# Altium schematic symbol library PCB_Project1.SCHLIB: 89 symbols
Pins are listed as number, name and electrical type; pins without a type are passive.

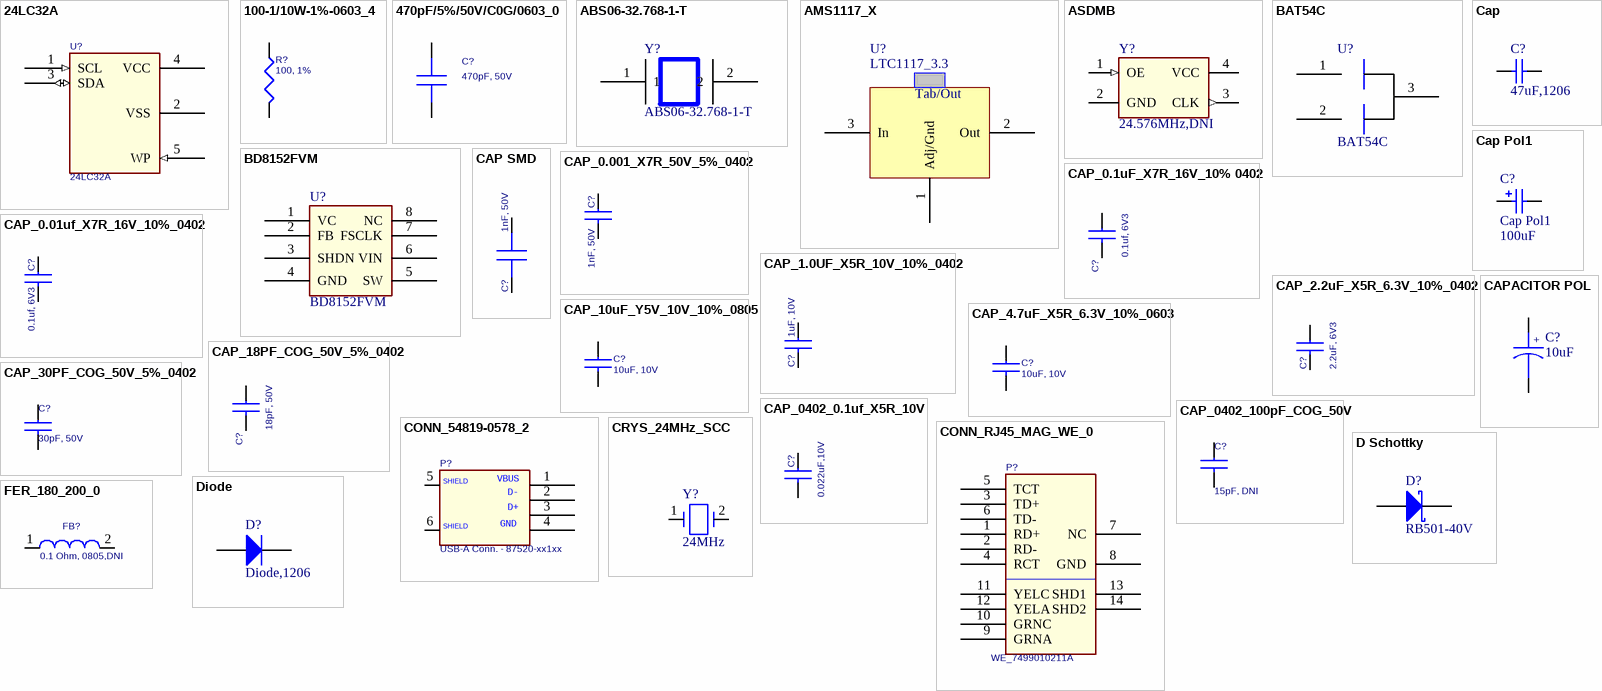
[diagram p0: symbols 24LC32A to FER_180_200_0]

## 24LC32A
designator U?
IC EEPROM 32KBIT 400KHZ SOT23-5; Manufacturer: Microchip Technology; Manufacturer Part Number: 24LC32AT-I/OT; Format - Memory: EEPROMs - Serial; Memory Size: 32K (4K x 8); Interface: I²C, 2-Wire Serial; Voltage - Supply: 2.5 V ~ 5.5 V
footprint SOT23-5/24LC32AT-I /SOT-23-5 (Footprint not found)
pins: 1 SCL (in), 2 VSS (power), 3 SDA (io), 4 VCC (power), 5 WP (in)

## 100-1/10W-1%-0603_4
designator R?, comment 100, 1%
RES 100 OHM 1/10W 5% 0402 SMD; PART#: Rohm MCR03EZPFX1000; Manufacturer: Panasonic Electronic Components; Manufacturer Part Number: ERJ-2RKF1000X; Resistance (Ohms): 100; Power (Watts): 0.1W, 1/10W; Temperature Coefficient: ?00ppm/°C
footprint 402
footprint R0402
pins: 1, 2

## 470pF/5%/50V/C0G/0603_0
designator C?, comment 470pF, 50V
CAP CER 470PF 50V 10% X7R 0402; Manufacturer: Murata Electronics North America; Manufacturer Part Number: GRM155R71H471KA01D; Tolerance: ?0%
footprint 402
footprint 402
pins: 1, 2

## ABS06-32.768-1-T
designator Y?
footprint SMD/ABS06-32.768KHZ-1-T (Footprint not found)
pins: 1, 2

## AMS1117_X
designator U?, comment LTC1117_3.3
footprint SOT223
pins: 1 Adj/Gnd, 2 Out, 3 In

## ASDMB
designator Y?, comment 24.576MHz,DNI
Manufacturer: Abracon Corporation; Manufacturer Part Number: ASDMB-24.576MHZ-LC-T; Function: Standby (Power Down); Output: CMOS; Voltage - Supply: 1.8 V ~ 3.3 V; Frequency Stability: ?0ppm; Current - Supply (Max): 16mA; Current - Supply (Disable) (Max): 15µA
footprint OSC4_61X65LS_79X98SMD
pins: 1 OE (in), 2 GND (power), 3 CLK (out), 4 VCC (power)

## BAT54C
designator U?
footprint SOT-23/BAT54C (Footprint not found)
pins: 1, 2, 3

## BD8152FVM
designator U?
footprint MSOP8/BD8152FVM (Footprint not found)
pins: 1 VC, 2 FB, 3 SHDN, 4 GND, 5 SW, 6 VIN, 7 FSCLK, 8 NC

## Cap
designator C?, comment 47uF,1206
Capacitor
footprint 1206 (Footprint not found)
pins: 1, 2

## Cap Pol1
designator C?  value 100uF
Polarized Capacitor (Radial)
simulation model CAP (Capacitor)
signal-integrity model Cap Pol
footprint RD205SMD_250D (Footprint not found)
pins: 1, 2
1 alternate drawing of the same symbol

## CAP SMD
designator C?, comment 1nF, 50V
CAP CER 1000PF 16V 10% X7R 0402; Manufacturer: Yageo; Manufacturer Part Number: CC0402KRX7R7BB102; Tolerance: ?0%
footprint 402
pins: 1, 2

## CAP_0.001_X7R_50V_5%_0402
designator C?, comment 1nF, 50V
CAP CER 1000PF 16V 10% X7R 0402; Manufacturer: Yageo; Manufacturer Part Number: CC0402KRX7R7BB102; Tolerance: ?0%
footprint 402
footprint 402
pins: 1, 2

## CAP_0.1uF_X7R_16V_10% 0402
designator C?, comment 0.1uf, 6V3
CAP CER 0.1UF 6.3V 10% X5R 0402; Manufacturer: TDK Corporation; Manufacturer Part Number: C1005X5R0J104K050BA; Capacitance: 0.1µF; Tolerance: ?0%
footprint 402
footprint 402
pins: 1, 2

## CAP_0.01uf_X7R_16V_10%_0402
designator C?, comment 0.1uf, 6V3
CAP CER 0.1UF 6.3V 10% X5R 0402; Manufacturer: TDK Corporation; Manufacturer Part Number: C1005X5R0J104K050BA; Capacitance: 0.1µF; Tolerance: ?0%
footprint 402
footprint 402
pins: 1, 2

## CAP_1.0UF_X5R_10V_10%_0402
designator C?, comment 1uF, 10V
CAP CER 1UF 10V 10% X5R 0402; Manufacturer: AVX Corporation; Manufacturer Part Number: 0402ZD105KAT2A; Capacitance: 1.0µF; Tolerance: ?0%
footprint 402
footprint 402
pins: 1, 2

## CAP_2.2uF_X5R_6.3V_10%_0402
designator C?, comment 2.2uF, 6V3
CAP CER 2.2UF 6.3V 10% X5R 0402; Manufacturer: TDK Corporation; Manufacturer Part Number: C1005X5R0J225K050BC; Capacitance: 2.2µF; Tolerance: ?0%
footprint 0805 (Footprint not found)
footprint 402
pins: 1, 2

## CAP_4.7uF_X5R_6.3V_10%_0603
designator C?, comment 10uF, 10V
CAP CER 10UF 10V Y5V 0805; Manufacturer: TDK Corporation; Manufacturer Part Number: C2012Y5V1A106Z; Capacitance: 10µF; Tolerance: -20%, +80%; Temperature Coefficient: Y5V (F)
footprint 805
pins: 1, 2

## CAP_10uF_Y5V_10V_10%_0805
designator C?, comment 10uF, 10V
CAP CER 10UF 10V Y5V 0805; Manufacturer: TDK Corporation; Manufacturer Part Number: C2012Y5V1A106Z; Capacitance: 10µF; Tolerance: -20%, +80%; Temperature Coefficient: Y5V (F)
footprint 805
pins: 1, 2

## CAP_18PF_COG_50V_5%_0402
designator C?, comment 18pF, 50V
CAP CER 18PF 50V 5% NP0 0402; Manufacturer: TDK Corporation; Manufacturer Part Number: C1005C0G1H180J050BA; Tolerance: ?%; Temperature Coefficient: C0G, NP0
footprint 402
footprint 402
pins: 1, 2

## CAP_30PF_COG_50V_5%_0402
designator C?, comment 30pF, 50V
CAP CER 30PF 50V 5% NP0 0402; Manufacturer: TDK Corporation; Manufacturer Part Number: C1005C0G1H300J; Tolerance: ?%; Temperature Coefficient: C0G, NP0
footprint 402
footprint 402
pins: 1, 2

## CAP_0402_0.1uf_X5R_10V
designator C?, comment 0.022uF,10V
CAP CER 0.022UF 10V 10% X7R 0402; Manufacturer: Taiyo Yuden; Manufacturer Part Number: LMK105B7223KV-F; Capacitance: 0.022µF; Tolerance: ?0%
footprint 402
pins: 1, 2

## CAP_0402_100pF_COG_50V
designator C?, comment 15pF, DNI
CAP CER 15PF 50V 5% NP0 0402; Manufacturer: TDK Corporation; Manufacturer Part Number: C1005C0G1H150J050BA; Tolerance: ?%; Temperature Coefficient: C0G, NP0
footprint 402
pins: 1, 2

## CAPACITOR POL
designator C?, comment 10uF
Capacitor
footprint 3528T (Footprint not found)
pins: 1, 2

## CONN_54819-0578_2
designator P?, comment USB-A Conn. - 87520-xx1xx
CONN RCPT USB TYPE A R/A PCB; Manufacturer: FCI; Manufacturer Part Number: 87520-0010BLF; CLASS: IO; TN: 224-0234-000; Number of Contacts: 4; Gender: Receptacle; Specifications: USB 2.0
footprint usb_a_sh
pins: 1 P1, 2 P2, 3 P3, 4 P4, 5 SHELD1, 6 PAD4

## CONN_RJ45_MAG_WE_0
designator P?, comment WE_7499010211A
WE-RJ45 LAN Transformer
footprint RJ45-BEL_J1-SHLD
footprint RJ45-7499010211A
pins: 1 RD+, 2 RD-, 3 TD+, 4 RCT, 5 TCT, 6 TD-, 7 NC, 8 GND, 9 GRNA, 10 GRNC, 11 YELC, 12 YELA, 13 SHD1, 14 SHD2

## CRYS_24MHz_SCC
designator Y?, comment 24MHz
CRYSTAL 24.000MHZ 18PF SMD; Manufacturer: TXC CORPORATION; Manufacturer Part Number: 7A-24.000MAAJ-T; Frequency Stability: ?0ppm; ESR (Equivalent Series Resistance): 50 Ohm; Operating Mode: Fundamental
footprint XTAL150SMD_125X196
pins: 1, 2

## D Schottky
designator D?, comment RB501-40V
Schottky Diode
footprint DSO-C2/X2.3 (DO-214-AA/SMB; 2 C-Bend Leads; Body 5.3 x 3.6 mm, inc. leads (LxW))
simulation model SKYDIODE (Diode)
signal-integrity model D Schottky
pins: 1 A, 2 K

## Diode
designator D?, comment Diode,1206
Default Diode
simulation model DIODE (Diode)
signal-integrity model Diode
footprint 1206P (Footprint not found)
pins: 1 A, 2 K

## FER_180_200_0
designator FB?, comment 0.1 Ohm, 0805,DNI
RES .10 OHM 1/8W 5% 0805; Manufacturer: CTS Resistor Products; Manufacturer Part Number: 73L3R10J; Resistance (Ohms): 0.1; Power (Watts): 0.125W, 1/8W; Temperature Coefficient: ?00ppm/°C; Tolerance: ?%
footprint SM-7351-IND-0805
pins: 1, 2

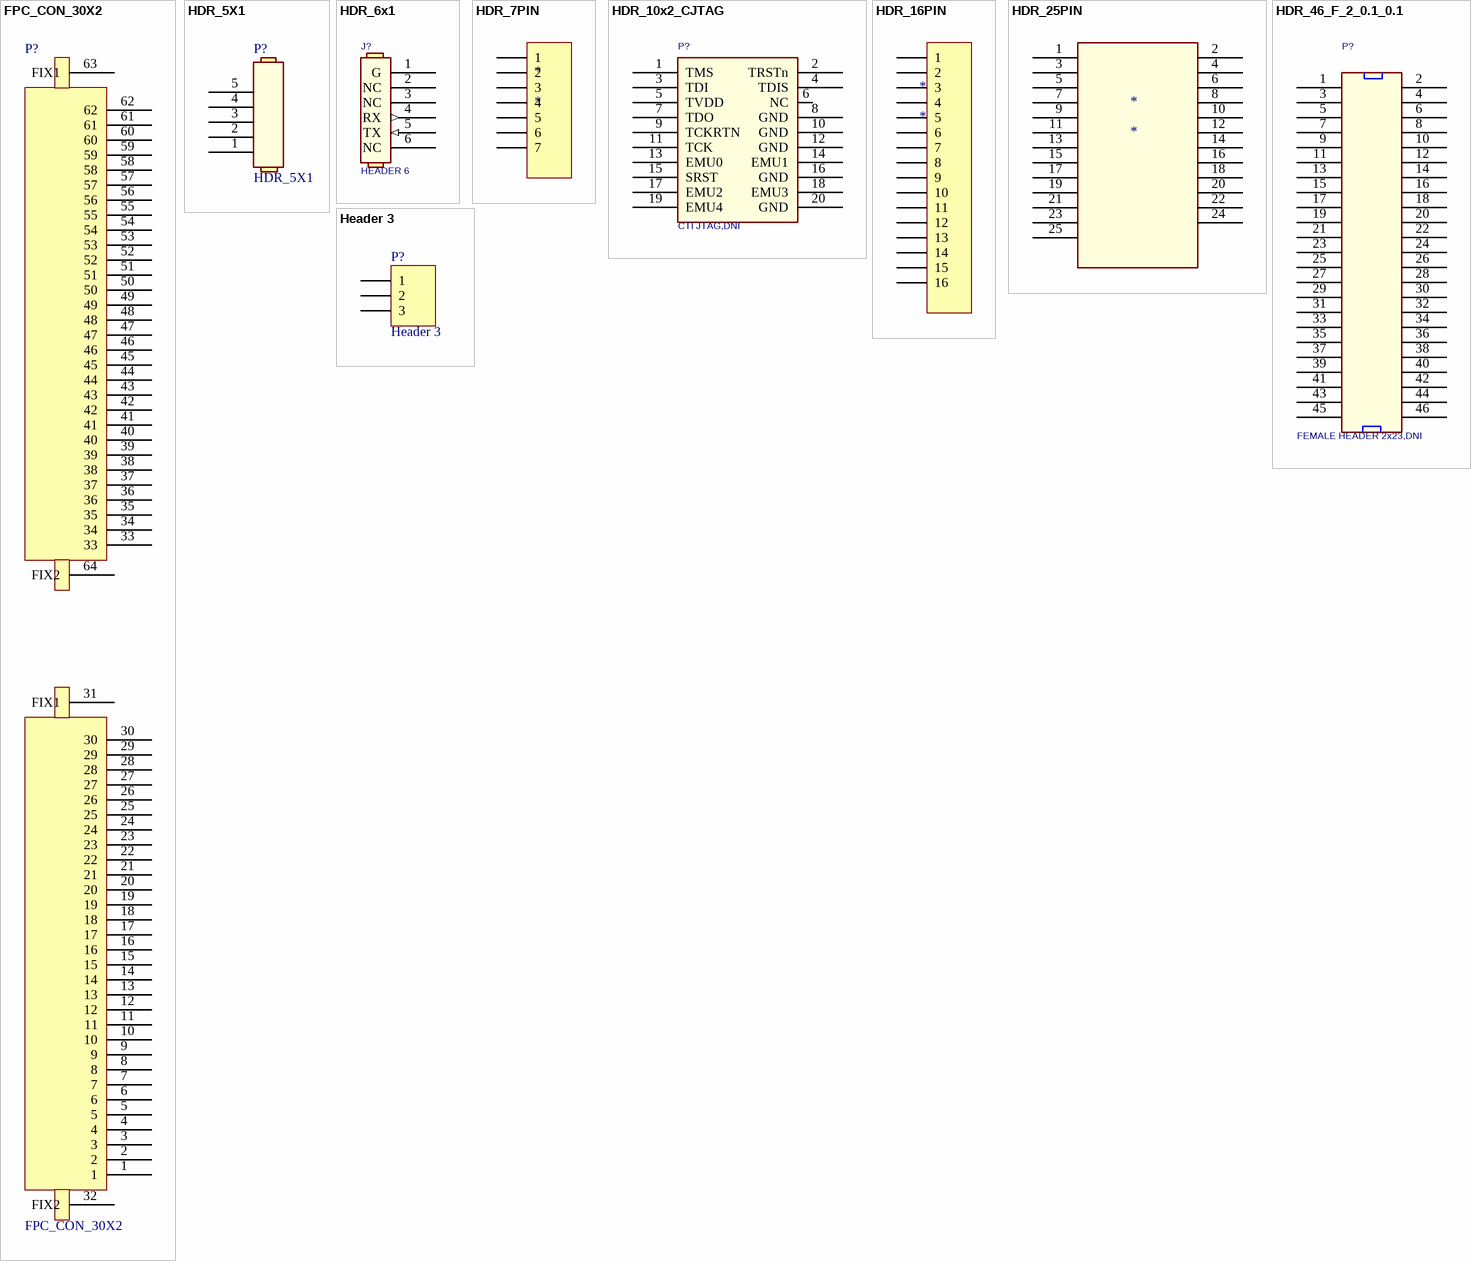
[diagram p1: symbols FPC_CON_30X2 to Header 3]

## FPC_CON_30X2
designator P?
footprint FPC_CON_30X2 (Footprint not found)
pins: 1, 2, 3, 4, 5, 6, 7, 8, 9, 10, 11, 12, 13, 14, 15, 16, 17, 18, 19, 20, 21, 22, 23, 24, 25, 26, 27, 28, 29, 30, 31 FIX1, 32 FIX2, 33, 34, 35, 36, 37, 38, 39, 40, 41, 42, 43, 44, 45, 46, 47, 48, 49, 50, 51, 52, 53, 54, 55, 56, 57, 58, 59, 60, 61, 62, 63 FIX1, 64 FIX2

## HDR_5X1
designator P?
footprint HDR_5X1 (Footprint not found)
pins: 1 (power), 2, 3, 4, 5

## HDR_6x1
designator J?, comment HEADER 6
CONN HEADER 6POS, VERTICAL,  .100 STR TIN; Manufacturer: Samtec Inc; Manufacturer Part Number: FTR-110-03-G-D-06; Connector Type: Unshrouded; Number of Positions: 20; Number of Positions Loaded: 19; Pitch: 0.050" (1.27mm); Row Spacing: 0.100" (2.54mm)
footprint SIP6
pins: 1 G (power), 2 NC, 3 NC, 4 RX (out), 5 TX (in), 6 NC

## HDR_7PIN
designator *
pins: 1, 2, 3, 4, 5, 6, 7

## HDR_10x2_CJTAG
designator P?, comment CTI JTAG,DNI
Dual Line Header 10x2pin Tin; Manufacturer: Samtec Inc; Manufacturer Part Number: FTR-110-03-G-D-06; Connector Type: Unshrouded; Number of Positions: 20; Number of Positions Loaded: 19; Pitch: 0.050" (1.27mm); Row Spacing: 0.100" (2.54mm)
footprint HEADER10X2_SMD
pins: 1 TMS, 2 TRSTn, 3 TDI, 4 TDIS, 5 TVDD, 6 NC, 7 TDO, 8 GND (power), 9 TCKRTN, 10 GND (power), 11 TCK, 12 GND (power), 13 EMU0, 14 EMU1, 15 SRST, 16 GND (power), 17 EMU2, 18 EMU3, 19 EMU4, 20 GND (power)

## HDR_16PIN
designator *
pins: 1, 2, 3, 4, 5, 6, 7, 8, 9, 10, 11, 12, 13, 14, 15, 16

## HDR_25PIN
designator *
pins: 1, 2, 3, 4, 5, 6, 7, 8, 9, 10 (power), 11, 12 (power), 13, 14, 15, 16 (power), 17, 18, 19, 20 (power), 21, 22 (power), 23, 24, 25

## HDR_46_F_2_0.1_0.1
designator P?, comment FEMALE HEADER 2x23,DNI
CONN HEADER FMAL 46PS.1" DL GOLD; Manufacturer: Sullins Connector Solutions; Manufacturer Part Number: PPPC232LFBN-RC; Number of Positions: 46; Number of Positions Loaded: All; Pitch: 0.100" (2.54mm)
footprint HEADER23X2
pins: 1, 2 26, 3 2, 4 27, 5 3, 6 28, 7 4, 8 29, 9 5, 10 30, 11 6, 12 31, 13 7, 14 32, 15 8, 16 33, 17 9, 18 34, 19 10, 20 35, 21 11, 22 36, 23 12, 24 37, 25 13, 26 38, 27 14, 28 39, 29 15, 30 40, 31 16, 32 41, 33 17, 34 42, 35 18, 36 43, 37 19, 38 44, 39 20, 40 45, 41 21, 42 46, 43 22, 44 47, 45 23, 46 48

## Header 3
designator P?
Header, 3-Pin
footprint HDR1X3 (Connector; Header; 3 Position)
signal-integrity model Connector
pins: 1, 2, 3

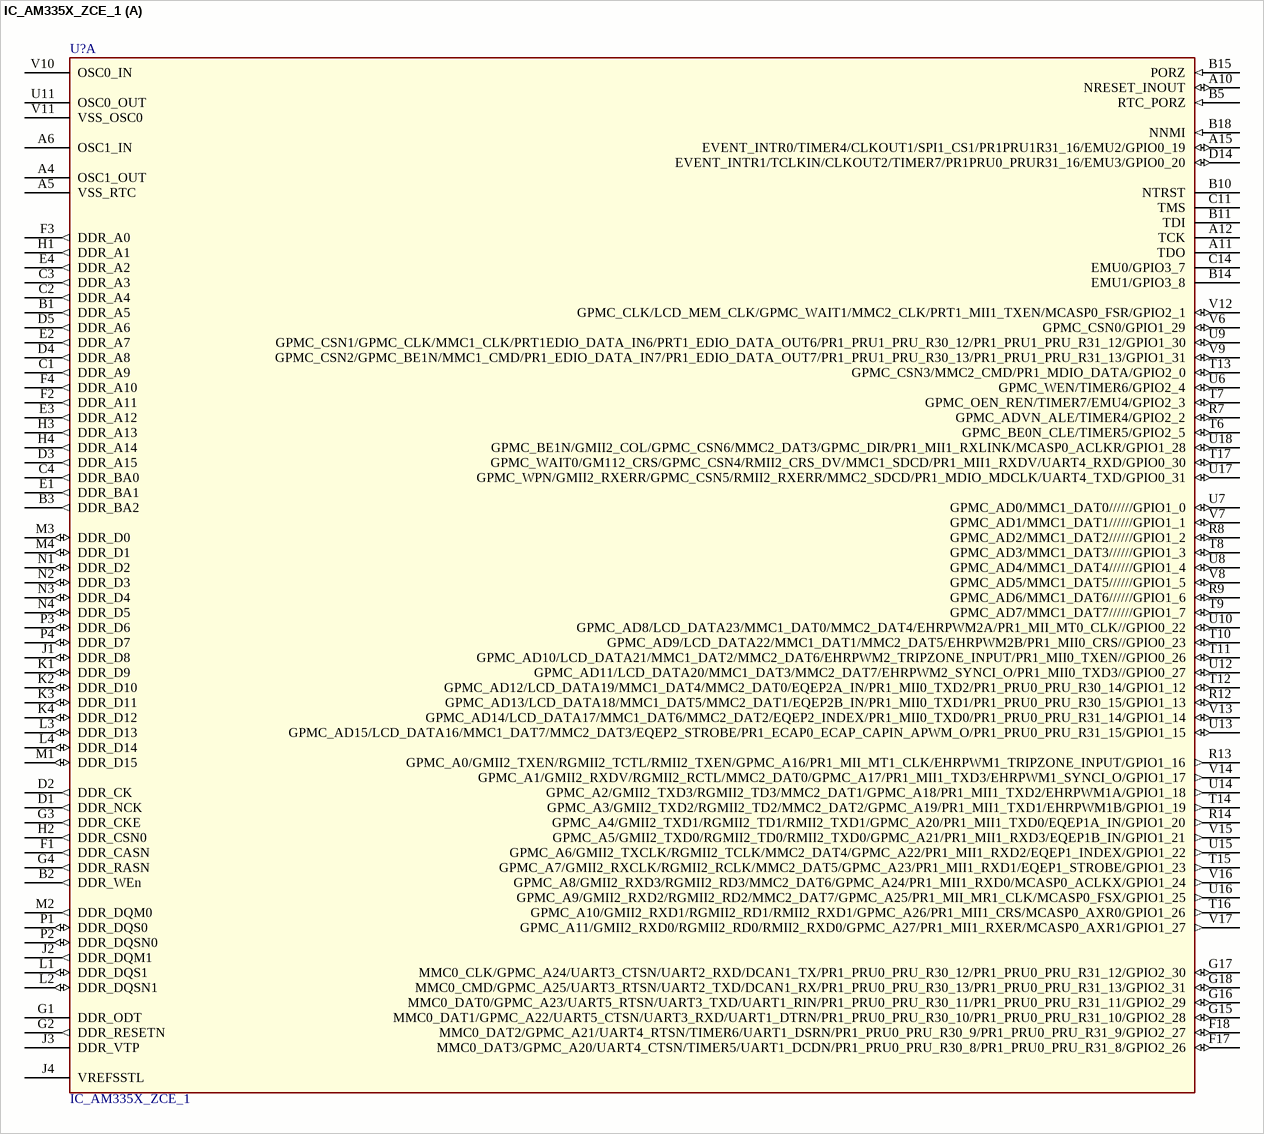
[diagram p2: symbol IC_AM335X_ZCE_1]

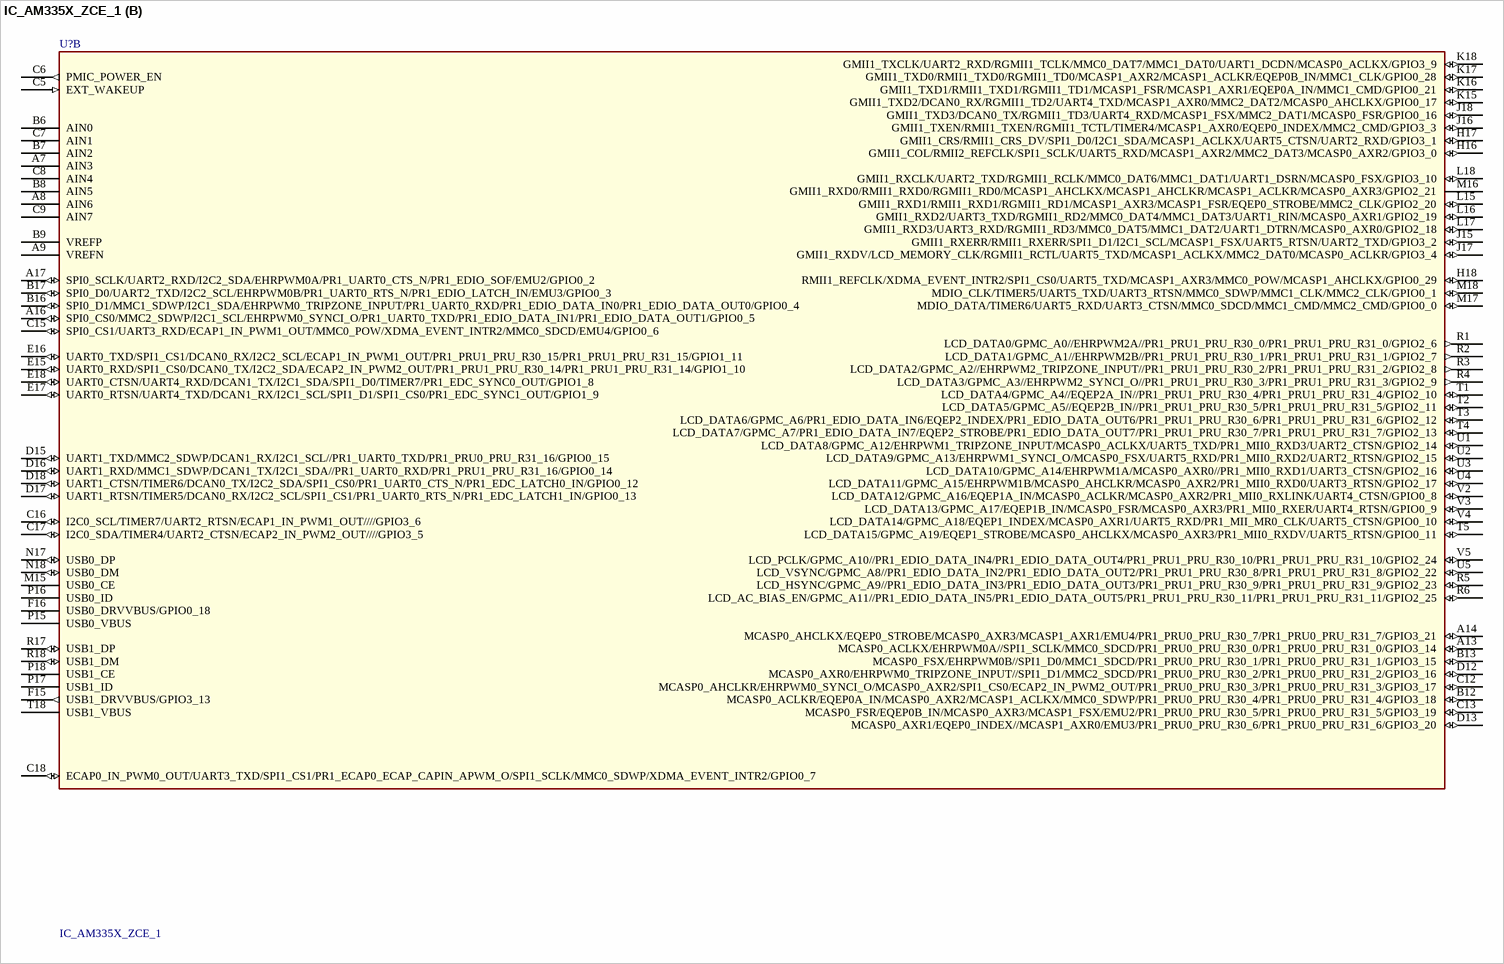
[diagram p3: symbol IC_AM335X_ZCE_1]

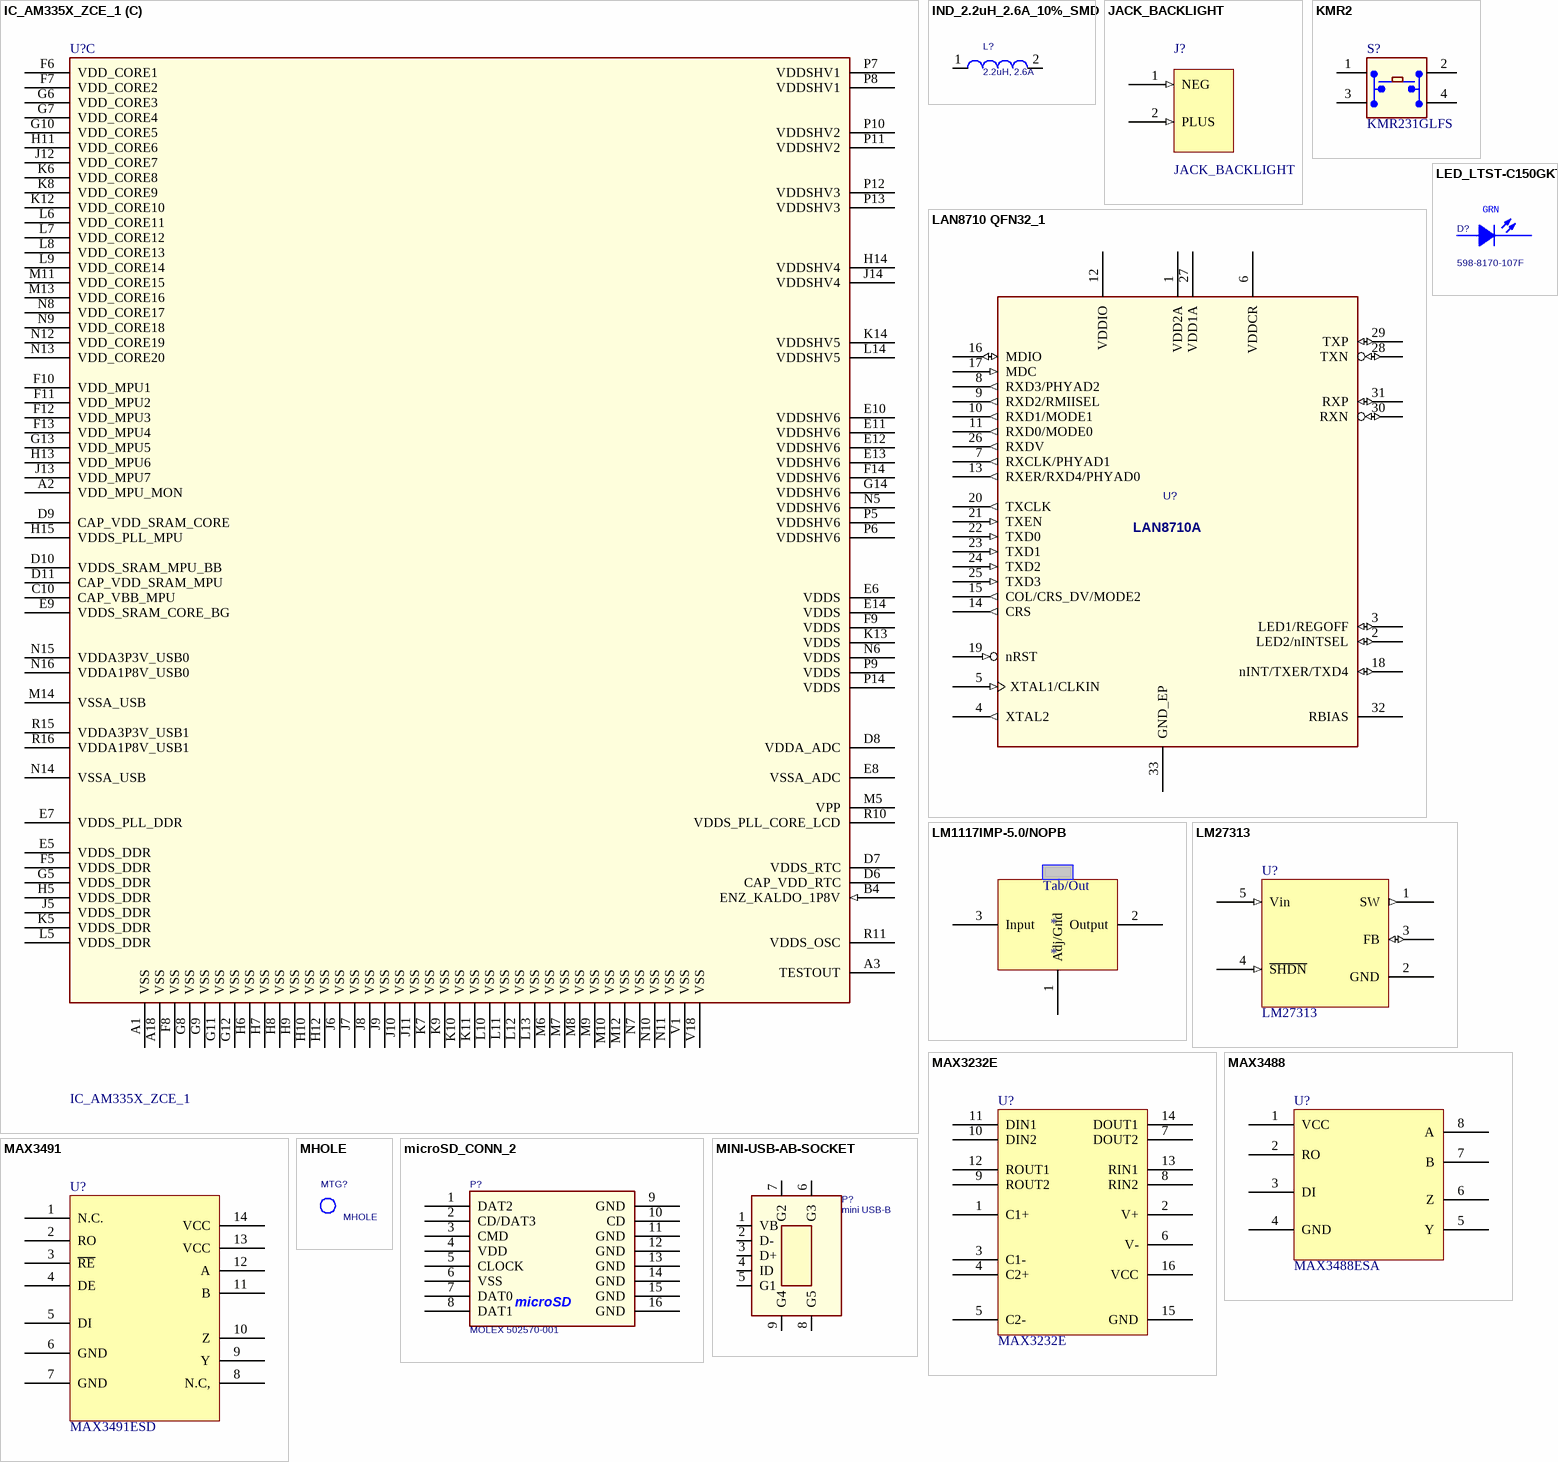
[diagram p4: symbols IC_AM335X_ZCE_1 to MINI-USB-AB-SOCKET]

## IC_AM335X_ZCE_1
designator U?
SubArctic Cortex A8 Processor 15x15; Manufacturer: Texas Instruments; Manufacturer Part Number: XAM3359ZCZ; Processor Type: ARM Microprocessor; Voltage: 1.06 V ~ 1.15 V
footprint am33xx_15x15/AM3354ZCZD72/324-NFBGA (Footprint not found)
part A pins: A4 OSC1_OUT, A5 VSS_RTC (power), A6 OSC1_IN, A10 NRESET_INOUT (io), A11 TDO, A12 TCK, A15 EVENT_INTR0/TIMER4/CLKOUT1/SPI1_CS1/PR1PRU1R31_16/EMU2/GPIO0_19 (io), B1 DDR_A5 (out), B2 DDR_WEn (out), B3 DDR_BA2 (out), B5 RTC_PORZ (in), B10 NTRST, B11 TDI, B14 EMU1/GPIO3_8, B15 PORZ (in), B18 NNMI (in), C1 DDR_A9 (out), C2 DDR_A4 (out), C3 DDR_A3 (out), C4 DDR_BA0 (out), C11 TMS, C14 EMU0/GPIO3_7, D1 DDR_NCK (out), D2 DDR_CK (out), D3 DDR_A15 (out), D4 DDR_A8 (out), D5 DDR_A6 (out), D14 EVENT_INTR1/TCLKIN/CLKOUT2/TIMER7/PR1PRU0_PRUR31_16/EMU3/GPIO0_20 (io), E1 DDR_BA1 (out), E2 DDR_A7 (out), E3 DDR_A12 (out), E4 DDR_A2 (out), F1 DDR_CASN (out), F2 DDR_A11 (out), F3 DDR_A0 (out), F4 DDR_A10 (out), F17 MMC0_DAT3/GPMC_A20/UART4_CTSN/TIMER5/UART1_DCDN/PR1_PRU0_PRU_R30_8/PR1_PRU0_PRU_R31_8/GPIO2_26 (io), F18 MMC0_DAT2/GPMC_A21/UART4_RTSN/TIMER6/UART1_DSRN/PR1_PRU0_PRU_R30_9/PR1_PRU0_PRU_R31_9/GPIO2_27 (io), G1 DDR_ODT, G2 DDR_RESETN (out), G3 DDR_CKE (out), G4 DDR_RASN (out), G15 MMC0_DAT1/GPMC_A22/UART5_CTSN/UART3_RXD/UART1_DTRN/PR1_PRU0_PRU_R30_10/PR1_PRU0_PRU_R31_10/GPIO2_28 (io), G16 MMC0_DAT0/GPMC_A23/UART5_RTSN/UART3_TXD/UART1_RIN/PR1_PRU0_PRU_R30_11/PR1_PRU0_PRU_R31_11/GPIO2_29 (io), G17 MMC0_CLK/GPMC_A24/UART3_CTSN/UART2_RXD/DCAN1_TX/PR1_PRU0_PRU_R30_12/PR1_PRU0_PRU_R31_12/GPIO2_30 (io), G18 MMC0_CMD/GPMC_A25/UART3_RTSN/UART2_TXD/DCAN1_RX/PR1_PRU0_PRU_R30_13/PR1_PRU0_PRU_R31_13/GPIO2_31 (io), H1 DDR_A1 (out), H2 DDR_CSN0 (out), H3 DDR_A13 (out), H4 DDR_A14 (out), J1 DDR_D8 (io), J2 DDR_DQM1 (out), J3 DDR_VTP, J4 VREFSSTL, K1 DDR_D9 (io), K2 DDR_D10 (io), K3 DDR_D11 (io), K4 DDR_D12 (io), L1 DDR_DQS1 (io), L2 DDR_DQSN1 (io), L3 DDR_D13 (io), L4 DDR_D14 (io), M1 DDR_D15 (io), M2 DDR_DQM0 (out), M3 DDR_D0 (io), M4 DDR_D1 (io), N1 DDR_D2 (io), N2 DDR_D3 (io), N3 DDR_D4 (io), N4 DDR_D5 (io), P1 DDR_DQS0 (io), P2 DDR_DQSN0 (io), P3 DDR_D6 (io), P4 DDR_D7 (io), R7 GPMC_ADVN_ALE/TIMER4/GPIO2_2 (io), R8 GPMC_AD2/MMC1_DAT2//////GPIO1_2 (io), R9 GPMC_AD6/MMC1_DAT6//////GPIO1_6 (io), R12 GPMC_AD13/LCD_DATA18/MMC1_DAT5/MMC2_DAT1/EQEP2B_IN/PR1_MII0_TXD1/PR1_PRU0_PRU_R30_15/GPIO1_13 (io), R13 GPMC_A0/GMII2_TXEN/RGMII2_TCTL/RMII2_TXEN/GPMC_A16/PR1_MII_MT1_CLK/EHRPWM1_TRIPZONE_INPUT/GPIO1_16 (out), R14 GPMC_A4/GMII2_TXD1/RGMII2_TD1/RMII2_TXD1/GPMC_A20/PR1_MII1_TXD0/EQEP1A_IN/GPIO1_20 (out), T6 GPMC_BE0N_CLE/TIMER5/GPIO2_5 (io), T7 GPMC_OEN_REN/TIMER7/EMU4/GPIO2_3 (io), T8 GPMC_AD3/MMC1_DAT3//////GPIO1_3 (io), T9 GPMC_AD7/MMC1_DAT7//////GPIO1_7 (io), T10 GPMC_AD9/LCD_DATA22/MMC1_DAT1/MMC2_DAT5/EHRPWM2B/PR1_MII0_CRS//GPIO0_23 (io), T11 GPMC_AD10/LCD_DATA21/MMC1_DAT2/MMC2_DAT6/EHRPWM2_TRIPZONE_INPUT/PR1_MII0_TXEN//GPIO0_26 (io), T12 GPMC_AD12/LCD_DATA19/MMC1_DAT4/MMC2_DAT0/EQEP2A_IN/PR1_MII0_TXD2/PR1_PRU0_PRU_R30_14/GPIO1_12 (io), T13 GPMC_CSN3/MMC2_CMD/PR1_MDIO_DATA/GPIO2_0 (io), T14 GPMC_A3/GMII2_TXD2/RGMII2_TD2/MMC2_DAT2/GPMC_A19/PR1_MII1_TXD1/EHRPWM1B/GPIO1_19 (out), T15 GPMC_A7/GMII2_RXCLK/RGMII2_RCLK/MMC2_DAT5/GPMC_A23/PR1_MII1_RXD1/EQEP1_STROBE/GPIO1_23 (out), T16 GPMC_A10/GMII2_RXD1/RGMII2_RD1/RMII2_RXD1/GPMC_A26/PR1_MII1_CRS/MCASP0_AXR0/GPIO1_26 (out), T17 GPMC_WAIT0/GM112_CRS/GPMC_CSN4/RMII2_CRS_DV/MMC1_SDCD/PR1_MII1_RXDV/UART4_RXD/GPIO0_30 (io), U6 GPMC_WEN/TIMER6/GPIO2_4 (io), U7 GPMC_AD0/MMC1_DAT0//////GPIO1_0 (io), U8 GPMC_AD4/MMC1_DAT4//////GPIO1_4 (io), U9 GPMC_CSN1/GPMC_CLK/MMC1_CLK/PRT1EDIO_DATA_IN6/PRT1_EDIO_DATA_OUT6/PR1_PRU1_PRU_R30_12/PR1_PRU1_PRU_R31_12/GPIO1_30 (io), U10 GPMC_AD8/LCD_DATA23/MMC1_DAT0/MMC2_DAT4/EHRPWM2A/PR1_MII_MT0_CLK//GPIO0_22 (io), U11 OSC0_OUT, U12 GPMC_AD11/LCD_DATA20/MMC1_DAT3/MMC2_DAT7/EHRPWM2_SYNCI_O/PR1_MII0_TXD3//GPIO0_27 (io), U13 GPMC_AD15/LCD_DATA16/MMC1_DAT7/MMC2_DAT3/EQEP2_STROBE/PR1_ECAP0_ECAP_CAPIN_APWM_O/PR1_PRU0_PRU_R31_15/GPIO1_15 (io), U14 GPMC_A2/GMII2_TXD3/RGMII2_TD3/MMC2_DAT1/GPMC_A18/PR1_MII1_TXD2/EHRPWM1A/GPIO1_18 (out), U15 GPMC_A6/GMII2_TXCLK/RGMII2_TCLK/MMC2_DAT4/GPMC_A22/PR1_MII1_RXD2/EQEP1_INDEX/GPIO1_22 (out), U16 GPMC_A9/GMII2_RXD2/RGMII2_RD2/MMC2_DAT7/GPMC_A25/PR1_MII_MR1_CLK/MCASP0_FSX/GPIO1_25 (out), U17 GPMC_WPN/GMII2_RXERR/GPMC_CSN5/RMII2_RXERR/MMC2_SDCD/PR1_MDIO_MDCLK/UART4_TXD/GPIO0_31 (io), U18 GPMC_BE1N/GMII2_COL/GPMC_CSN6/MMC2_DAT3/GPMC_DIR/PR1_MII1_RXLINK/MCASP0_ACLKR/GPIO1_28 (io), V6 GPMC_CSN0/GPIO1_29 (io), V7 GPMC_AD1/MMC1_DAT1//////GPIO1_1 (io), V8 GPMC_AD5/MMC1_DAT5//////GPIO1_5 (io), V9 GPMC_CSN2/GPMC_BE1N/MMC1_CMD/PR1_EDIO_DATA_IN7/PR1_EDIO_DATA_OUT7/PR1_PRU1_PRU_R30_13/PR1_PRU1_PRU_R31_13/GPIO1_31 (io), V10 OSC0_IN, V11 VSS_OSC0 (power), V12 GPMC_CLK/LCD_MEM_CLK/GPMC_WAIT1/MMC2_CLK/PRT1_MII1_TXEN/MCASP0_FSR/GPIO2_1 (io), V13 GPMC_AD14/LCD_DATA17/MMC1_DAT6/MMC2_DAT2/EQEP2_INDEX/PR1_MII0_TXD0/PR1_PRU0_PRU_R31_14/GPIO1_14 (io), V14 GPMC_A1/GMII2_RXDV/RGMII2_RCTL/MMC2_DAT0/GPMC_A17/PR1_MII1_TXD3/EHRPWM1_SYNCI_O/GPIO1_17 (out), V15 GPMC_A5/GMII2_TXD0/RGMII2_TD0/RMII2_TXD0/GPMC_A21/PR1_MII1_RXD3/EQEP1B_IN/GPIO1_21 (out), V16 GPMC_A8/GMII2_RXD3/RGMII2_RD3/MMC2_DAT6/GPMC_A24/PR1_MII1_RXD0/MCASP0_ACLKX/GPIO1_24 (out), V17 GPMC_A11/GMII2_RXD0/RGMII2_RD0/RMII2_RXD0/GPMC_A27/PR1_MII1_RXER/MCASP0_AXR1/GPIO1_27 (out)
part B pins: A7 AIN3, A8 AIN6, A9 VREFN, A13 MCASP0_ACLKX/EHRPWM0A//SPI1_SCLK/MMC0_SDCD/PR1_PRU0_PRU_R30_0/PR1_PRU0_PRU_R31_0/GPIO3_14 (io), A14 MCASP0_AHCLKX/EQEP0_STROBE/MCASP0_AXR3/MCASP1_AXR1/EMU4/PR1_PRU0_PRU_R30_7/PR1_PRU0_PRU_R31_7/GPIO3_21 (io), A16 SPI0_CS0/MMC2_SDWP/I2C1_SCL/EHRPWM0_SYNCI_O/PR1_UART0_TXD/PR1_EDIO_DATA_IN1/PR1_EDIO_DATA_OUT1/GPIO0_5 (io), A17 SPI0_SCLK/UART2_RXD/I2C2_SDA/EHRPWM0A/PR1_UART0_CTS_N/PR1_EDIO_SOF/EMU2/GPIO0_2 (io), B6 AIN0, B7 AIN2, B8 AIN5, B9 VREFP, B12 MCASP0_ACLKR/EQEP0A_IN/MCASP0_AXR2/MCASP1_ACLKX/MMC0_SDWP/PR1_PRU0_PRU_R30_4/PR1_PRU0_PRU_R31_4/GPIO3_18 (io), B13 MCASP0_FSX/EHRPWM0B//SPI1_D0/MMC1_SDCD/PR1_PRU0_PRU_R30_1/PR1_PRU0_PRU_R31_1/GPIO3_15 (io), B16 SPI0_D1/MMC1_SDWP/I2C1_SDA/EHRPWM0_TRIPZONE_INPUT/PR1_UART0_RXD/PR1_EDIO_DATA_IN0/PR1_EDIO_DATA_OUT0/GPIO0_4 (io), B17 SPI0_D0/UART2_TXD/I2C2_SCL/EHRPWM0B/PR1_UART0_RTS_N/PR1_EDIO_LATCH_IN/EMU3/GPIO0_3 (io), C5 EXT_WAKEUP (in), C6 PMIC_POWER_EN (out), C7 AIN1, C8 AIN4, C9 AIN7, C12 MCASP0_AHCLKR/EHRPWM0_SYNCI_O/MCASP0_AXR2/SPI1_CS0/ECAP2_IN_PWM2_OUT/PR1_PRU0_PRU_R30_3/PR1_PRU0_PRU_R31_3/GPIO3_17 (io), C13 MCASP0_FSR/EQEP0B_IN/MCASP0_AXR3/MCASP1_FSX/EMU2/PR1_PRU0_PRU_R30_5/PR1_PRU0_PRU_R31_5/GPIO3_19 (io), C15 SPI0_CS1/UART3_RXD/ECAP1_IN_PWM1_OUT/MMC0_POW/XDMA_EVENT_INTR2/MMC0_SDCD/EMU4/GPIO0_6 (io), C16 I2C0_SCL/TIMER7/UART2_RTSN/ECAP1_IN_PWM1_OUT////GPIO3_6 (io), C17 I2C0_SDA/TIMER4/UART2_CTSN/ECAP2_IN_PWM2_OUT////GPIO3_5 (io), C18 ECAP0_IN_PWM0_OUT/UART3_TXD/SPI1_CS1/PR1_ECAP0_ECAP_CAPIN_APWM_O/SPI1_SCLK/MMC0_SDWP/XDMA_EVENT_INTR2/GPIO0_7 (io), D12 MCASP0_AXR0/EHRPWM0_TRIPZONE_INPUT//SPI1_D1/MMC2_SDCD/PR1_PRU0_PRU_R30_2/PR1_PRU0_PRU_R31_2/GPIO3_16 (io), D13 MCASP0_AXR1/EQEP0_INDEX//MCASP1_AXR0/EMU3/PR1_PRU0_PRU_R30_6/PR1_PRU0_PRU_R31_6/GPIO3_20 (io), D15 UART1_TXD/MMC2_SDWP/DCAN1_RX/I2C1_SCL//PR1_UART0_TXD/PR1_PRU0_PRU_R31_16/GPIO0_15 (io), D16 UART1_RXD/MMC1_SDWP/DCAN1_TX/I2C1_SDA//PR1_UART0_RXD/PR1_PRU1_PRU_R31_16/GPIO0_14 (io), D17 UART1_RTSN/TIMER5/DCAN0_RX/I2C2_SCL/SPI1_CS1/PR1_UART0_RTS_N/PR1_EDC_LATCH1_IN/GPIO0_13 (io), D18 UART1_CTSN/TIMER6/DCAN0_TX/I2C2_SDA/SPI1_CS0/PR1_UART0_CTS_N/PR1_EDC_LATCH0_IN/GPIO0_12 (io), E15 UART0_RXD/SPI1_CS0/DCAN0_TX/I2C2_SDA/ECAP2_IN_PWM2_OUT/PR1_PRU1_PRU_R30_14/PR1_PRU1_PRU_R31_14/GPIO1_10 (io), E16 UART0_TXD/SPI1_CS1/DCAN0_RX/I2C2_SCL/ECAP1_IN_PWM1_OUT/PR1_PRU1_PRU_R30_15/PR1_PRU1_PRU_R31_15/GPIO1_11 (io), E17 UART0_RTSN/UART4_TXD/DCAN1_RX/I2C1_SCL/SPI1_D1/SPI1_CS0/PR1_EDC_SYNC1_OUT/GPIO1_9 (io), E18 UART0_CTSN/UART4_RXD/DCAN1_TX/I2C1_SDA/SPI1_D0/TIMER7/PR1_EDC_SYNC0_OUT/GPIO1_8 (io), F15 USB1_DRVVBUS/GPIO3_13 (out), F16 USB0_DRVVBUS/GPIO0_18, H16 GMII1_COL/RMII2_REFCLK/SPI1_SCLK/UART5_RXD/MCASP1_AXR2/MMC2_DAT3/MCASP0_AXR2/GPIO3_0 (io), H17 GMII1_CRS/RMII1_CRS_DV/SPI1_D0/I2C1_SDA/MCASP1_ACLKX/UART5_CTSN/UART2_RXD/GPIO3_1 (io), H18 RMII1_REFCLK/XDMA_EVENT_INTR2/SPI1_CS0/UART5_TXD/MCASP1_AXR3/MMC0_POW/MCASP1_AHCLKX/GPIO0_29 (io), J15 GMII1_RXERR/RMII1_RXERR/SPI1_D1/I2C1_SCL/MCASP1_FSX/UART5_RTSN/UART2_TXD/GPIO3_2 (io), J16 GMII1_TXEN/RMII1_TXEN/RGMII1_TCTL/TIMER4/MCASP1_AXR0/EQEP0_INDEX/MMC2_CMD/GPIO3_3 (io), J17 GMII1_RXDV/LCD_MEMORY_CLK/RGMII1_RCTL/UART5_TXD/MCASP1_ACLKX/MMC2_DAT0/MCASP0_ACLKR/GPIO3_4 (io), J18 GMII1_TXD3/DCAN0_TX/RGMII1_TD3/UART4_RXD/MCASP1_FSX/MMC2_DAT1/MCASP0_FSR/GPIO0_16 (io), K15 GMII1_TXD2/DCAN0_RX/RGMII1_TD2/UART4_TXD/MCASP1_AXR0/MMC2_DAT2/MCASP0_AHCLKX/GPIO0_17 (io), K16 GMII1_TXD1/RMII1_TXD1/RGMII1_TD1/MCASP1_FSR/MCASP1_AXR1/EQEP0A_IN/MMC1_CMD/GPIO0_21 (io), K17 GMII1_TXD0/RMII1_TXD0/RGMII1_TD0/MCASP1_AXR2/MCASP1_ACLKR/EQEP0B_IN/MMC1_CLK/GPIO0_28 (io), K18 GMII1_TXCLK/UART2_RXD/RGMII1_TCLK/MMC0_DAT7/MMC1_DAT0/UART1_DCDN/MCASP0_ACLKX/GPIO3_9 (io), L15 GMII1_RXD1/RMII1_RXD1/RGMII1_RD1/MCASP1_AXR3/MCASP1_FSR/EQEP0_STROBE/MMC2_CLK/GPIO2_20 (io), L16 GMII1_RXD2/UART3_TXD/RGMII1_RD2/MMC0_DAT4/MMC1_DAT3/UART1_RIN/MCASP0_AXR1/GPIO2_19 (io), L17 GMII1_RXD3/UART3_RXD/RGMII1_RD3/MMC0_DAT5/MMC1_DAT2/UART1_DTRN/MCASP0_AXR0/GPIO2_18 (io), L18 GMII1_RXCLK/UART2_TXD/RGMII1_RCLK/MMC0_DAT6/MMC1_DAT1/UART1_DSRN/MCASP0_FSX/GPIO3_10 (io), M15 USB0_CE, M16 GMII1_RXD0/RMII1_RXD0/RGMII1_RD0/MCASP1_AHCLKX/MCASP1_AHCLKR/MCASP1_ACLKR/MCASP0_AXR3/GPIO2_21, M17 MDIO_DATA/TIMER6/UART5_RXD/UART3_CTSN/MMC0_SDCD/MMC1_CMD/MMC2_CMD/GPIO0_0 (io), M18 MDIO_CLK/TIMER5/UART5_TXD/UART3_RTSN/MMC0_SDWP/MMC1_CLK/MMC2_CLK/GPIO0_1 (io), N17 USB0_DP (io), N18 USB0_DM (io), P15 USB0_VBUS, P16 USB0_ID, P17 USB1_ID, P18 USB1_CE, R1 LCD_DATA0/GPMC_A0//EHRPWM2A//PR1_PRU1_PRU_R30_0/PR1_PRU1_PRU_R31_0/GPIO2_6 (out), R2 LCD_DATA1/GPMC_A1//EHRPWM2B//PR1_PRU1_PRU_R30_1/PR1_PRU1_PRU_R31_1/GPIO2_7 (out), R3 LCD_DATA2/GPMC_A2//EHRPWM2_TRIPZONE_INPUT//PR1_PRU1_PRU_R30_2/PR1_PRU1_PRU_R31_2/GPIO2_8 (out), R4 LCD_DATA3/GPMC_A3//EHRPWM2_SYNCI_O//PR1_PRU1_PRU_R30_3/PR1_PRU1_PRU_R31_3/GPIO2_9 (out), R5 LCD_HSYNC/GPMC_A9//PR1_EDIO_DATA_IN3/PR1_EDIO_DATA_OUT3/PR1_PRU1_PRU_R30_9/PR1_PRU1_PRU_R31_9/GPIO2_23 (io), R6 LCD_AC_BIAS_EN/GPMC_A11//PR1_EDIO_DATA_IN5/PR1_EDIO_DATA_OUT5/PR1_PRU1_PRU_R30_11/PR1_PRU1_PRU_R31_11/GPIO2_25 (io), R17 USB1_DP (io), R18 USB1_DM (io), T1 LCD_DATA4/GPMC_A4//EQEP2A_IN//PR1_PRU1_PRU_R30_4/PR1_PRU1_PRU_R31_4/GPIO2_10 (io), T2 LCD_DATA5/GPMC_A5//EQEP2B_IN//PR1_PRU1_PRU_R30_5/PR1_PRU1_PRU_R31_5/GPIO2_11 (io), T3 LCD_DATA6/GPMC_A6/PR1_EDIO_DATA_IN6/EQEP2_INDEX/PR1_EDIO_DATA_OUT6/PR1_PRU1_PRU_R30_6/PR1_PRU1_PRU_R31_6/GPIO2_12 (io), T4 LCD_DATA7/GPMC_A7/PR1_EDIO_DATA_IN7/EQEP2_STROBE/PR1_EDIO_DATA_OUT7/PR1_PRU1_PRU_R30_7/PR1_PRU1_PRU_R31_7/GPIO2_13 (io), T5 LCD_DATA15/GPMC_A19/EQEP1_STROBE/MCASP0_AHCLKX/MCASP0_AXR3/PR1_MII0_RXDV/UART5_RTSN/GPIO0_11 (io), T18 USB1_VBUS, U1 LCD_DATA8/GPMC_A12/EHRPWM1_TRIPZONE_INPUT/MCASP0_ACLKX/UART5_TXD/PR1_MII0_RXD3/UART2_CTSN/GPIO2_14 (io), U2 LCD_DATA9/GPMC_A13/EHRPWM1_SYNCI_O/MCASP0_FSX/UART5_RXD/PR1_MII0_RXD2/UART2_RTSN/GPIO2_15 (io), U3 LCD_DATA10/GPMC_A14/EHRPWM1A/MCASP0_AXR0//PR1_MII0_RXD1/UART3_CTSN/GPIO2_16 (io), U4 LCD_DATA11/GPMC_A15/EHRPWM1B/MCASP0_AHCLKR/MCASP0_AXR2/PR1_MII0_RXD0/UART3_RTSN/GPIO2_17 (io), U5 LCD_VSYNC/GPMC_A8//PR1_EDIO_DATA_IN2/PR1_EDIO_DATA_OUT2/PR1_PRU1_PRU_R30_8/PR1_PRU1_PRU_R31_8/GPIO2_22 (io), V2 LCD_DATA12/GPMC_A16/EQEP1A_IN/MCASP0_ACLKR/MCASP0_AXR2/PR1_MII0_RXLINK/UART4_CTSN/GPIO0_8 (io), V3 LCD_DATA13/GPMC_A17/EQEP1B_IN/MCASP0_FSR/MCASP0_AXR3/PR1_MII0_RXER/UART4_RTSN/GPIO0_9 (io), V4 LCD_DATA14/GPMC_A18/EQEP1_INDEX/MCASP0_AXR1/UART5_RXD/PR1_MII_MR0_CLK/UART5_CTSN/GPIO0_10 (io), V5 LCD_PCLK/GPMC_A10//PR1_EDIO_DATA_IN4/PR1_EDIO_DATA_OUT4/PR1_PRU1_PRU_R30_10/PR1_PRU1_PRU_R31_10/GPIO2_24 (io)
part C pins: A1 VSS (power), A2 VDD_MPU_MON, A3 TESTOUT, A18 VSS (power), B4 ENZ_KALDO_1P8V (in), C10 CAP_VBB_MPU, D6 CAP_VDD_RTC (power), D7 VDDS_RTC (power), D8 VDDA_ADC (power), D9 CAP_VDD_SRAM_CORE (power), D10 VDDS_SRAM_MPU_BB (power), D11 CAP_VDD_SRAM_MPU (power), E5 VDDS_DDR (power), E6 VDDS (power), E7 VDDS_PLL_DDR (power), E8 VSSA_ADC (power), E9 VDDS_SRAM_CORE_BG (power), E10 VDDSHV6 (power), E11 VDDSHV6 (power), E12 VDDSHV6 (power), E13 VDDSHV6 (power), E14 VDDS (power), F5 VDDS_DDR (power), F6 VDD_CORE1 (power), F7 VDD_CORE2 (power), F8 VSS (power), F9 VDDS (power), F10 VDD_MPU1 (power), F11 VDD_MPU2 (power), F12 VDD_MPU3 (power), F13 VDD_MPU4 (power), F14 VDDSHV6 (power), G5 VDDS_DDR (power), G6 VDD_CORE3 (power), G7 VDD_CORE4 (power), G8 VSS (power), G9 VSS (power), G10 VDD_CORE5 (power), G11 VSS (power), G12 VSS (power), G13 VDD_MPU5 (power), G14 VDDSHV6 (power), H5 VDDS_DDR (power), H6 VSS (power), H7 VSS (power), H8 VSS (power), H9 VSS (power), H10 VSS (power), H11 VDD_CORE6 (power), H12 VSS (power), H13 VDD_MPU6 (power), H14 VDDSHV4 (power), H15 VDDS_PLL_MPU (power), J5 VDDS_DDR (power), J6 VSS (power), J7 VSS (power), J8 VSS (power), J9 VSS (power), J10 VSS (power), J11 VSS (power), J12 VDD_CORE7 (power), J13 VDD_MPU7 (power), J14 VDDSHV4 (power), K5 VDDS_DDR (power), K6 VDD_CORE8 (power), K7 VSS (power), K8 VDD_CORE9 (power), K9 VSS (power), K10 VSS (power), K11 VSS (power), K12 VDD_CORE10 (power), K13 VDDS (power), K14 VDDSHV5 (power), L5 VDDS_DDR (power), L6 VDD_CORE11 (power), L7 VDD_CORE12 (power), L8 VDD_CORE13 (power), L9 VDD_CORE14 (power), L10 VSS (power), L11 VSS (power), L12 VSS (power), L13 VSS (power), L14 VDDSHV5 (power), M5 VPP (power), M6 VSS (power), M7 VSS (power), M8 VSS (power), M9 VSS (power), M10 VSS (power), M11 VDD_CORE15 (power), M12 VSS (power), M13 VDD_CORE16 (power), M14 VSSA_USB (power), N5 VDDSHV6 (power), N6 VDDS (power), N7 VSS (power), N8 VDD_CORE17 (power), N9 VDD_CORE18 (power), N10 VSS (power), N11 VSS (power), N12 VDD_CORE19 (power), N13 VDD_CORE20 (power), N14 VSSA_USB (power), N15 VDDA3P3V_USB0 (power), N16 VDDA1P8V_USB0 (power), P5 VDDSHV6 (power), P6 VDDSHV6 (power), P7 VDDSHV1 (power), P8 VDDSHV1 (power), P9 VDDS (power), P10 VDDSHV2 (power), P11 VDDSHV2 (power), P12 VDDSHV3 (power), P13 VDDSHV3 (power), P14 VDDS (power), R10 VDDS_PLL_CORE_LCD (power), R11 VDDS_OSC (power), R15 VDDA3P3V_USB1 (power), R16 VDDA1P8V_USB1 (power), V1 VSS (power), V18 VSS (power)

## IND_2.2uH_2.6A_10%_SMD
designator L?, comment 2.2uH, 2.6A
INDUCTOR 2.2UH 20% 1300MA 1008; PartName: 2.2uH10%2.6Asmd; Mfr: TDK; MfrNum: VLCF5020T-2R2N2R6-3; TIIntPartnumber: 1L0025; Manufacturer: Murata Electronics North America; Manufacturer Part Number: LQM2HPN2R2MG0L; Vendor: Digikey; Cost100: 1.11; Cost10K: 0.37; Inductance: 2.2µH; Current Rating: 1.3A; Tolerance: ?0%; Shielding: Shielded; DC Resistance (DCR): 100 mOhm Max; Frequency - Self Resonant: 40MHz; Frequency - Test: 1MHz
footprint 2520
pins: 1, 2

## JACK_BACKLIGHT
designator J?
footprint JACK_BACKLIGHT (Footprint not found)
pins: 1 NEG (in), 2 PLUS (in)

## KMR2
designator S?, comment KMR231GLFS
Microminiature Tact Switch for SMT; Manufacturer: C&K Components; Circuit: SPST-NO; Switch Function: Off-Mom; Contact Rating @ Voltage: 0.05A @ 32VDC; Actuator Type: Standard; Actuator Height off PCB, from Pins: 1.90mm; Actuator Orientation: Top Actuated; Outline: 4.60mm x 2.80mm; Illumination: Non-Illuminated; Operating Force: 300gf; Switch Travel: 0.25mm; Mechanical Life: 150,000 Cycles
footprint SW4SMD_63X161LS
pins: 1 A1, 2 A2, 3 A3, 4 (power)

## LAN8710 QFN32_1
designator U?, comment LAN8710A
Ethernet ICs 10/100 Ethernet XCVR w/HPAutoMDIX FlexPwr; PART#: SMSC LAN8710A-EZK; Manufacturer: Microchip Technology; Manufacturer Part Number: LAN8710A-EZK-TR; Data Rate: 125 Mb/s; Number of Transceivers: 1; Standard Supported: 802.3, 802.3u; Supply Voltage - Max: 3.6 V; Supply Voltage - Min: 1.6 V, 3 V
footprint QFN32_5X5MM_EP3P3MM/LAN8710Ai-EZK/QFN-32 (Footprint not found)
footprint QFN32_5X5MM_EP3P3MM
pins: 1 VDD2A (power), 2 LED2/nINTSEL (io), 3 LED1/REGOFF (io), 4 XTAL2 (out), 5 XTAL1/CLKIN (in), 6 VDDCR (power), 7 RXCLK/PHYAD1 (out), 8 RXD3/PHYAD2 (out), 9 RXD2/RMIISEL (out), 10 RXD1/MODE1 (out), 11 RXD0/MODE0 (out), 12 VDDIO (power), 13 RXER/RXD4/PHYAD0 (out), 14 CRS (out), 15 COL/CRS_DV/MODE2 (out), 16 MDIO (io), 17 MDC (in), 18 nINT/TXER/TXD4 (io), 19 nRST (in), 20 TXCLK (out), 21 TXEN (in), 22 TXD0 (in), 23 TXD1 (in), 24 TXD2 (in), 25 TXD3 (in), 26 RXDV (out), 27 VDD1A (power), 28 TXN (io), 29 TXP (io), 30 RXN (io), 31 RXP (io), 32 RBIAS, 33 GND_EP (power)

## LED_LTST-C150GKT
designator D?, comment 598-8170-107F
LED GREEN CLEAR 0805 SMD; Manufacturer: Lite-On Inc; Manufacturer Part Number: LTST-C170KGKT; CLASS: DISCRETE; TN: 257-0020-000; Millicandela Rating: 35mcd; Voltage - Forward (Vf) Typ: 2V; Current - Test: 20mA; Wavelength - Dominant: 571nm; Wavelength - Peak: 574nm; Viewing Angle: 130; Lens Style/Size: Rectangle with Flat Top, 1.4mm x 1.25mm
footprint LED_0603
pins: 1 C, 2 A

## LM1117IMP-5.0/NOPB
designator *
pins: 1 Adj/Gnd, 2 Output, 3 Input

## LM27313
designator U?
footprint SOT23-5/LM27313 (Footprint not found)
pins: 1 SW (out), 2 GND, 3 FB (io), 4 ~{SHDN} (in), 5 Vin (in)

## MAX3232E
designator U?
footprint MAX3232EEA/SSOP16 (Footprint not found)
pins: 1 C1+, 2 V+, 3 C1-, 4 C2+, 5 C2-, 6 V-, 7 DOUT2, 8 RIN2, 9 ROUT2, 10 DIN2, 11 DIN1, 12 ROUT1, 13 RIN1, 14 DOUT1, 15 GND, 16 VCC

## MAX3488
designator U?, comment MAX3488ESA
footprint 8 SO (Footprint not found)
pins: 1 VCC, 2 RO, 3 DI, 4 GND, 5 Y, 6 Z, 7 B, 8 A

## MAX3491
designator U?, comment MAX3491ESD
footprint 14 SO (Footprint not found)
pins: 1 N.C., 2 RO, 3 ~{RE}, 4 DE, 5 DI, 6 GND, 7 GND, 8 N.C,, 9 Y, 10 Z, 11 B, 12 A, 13 VCC, 14 VCC

## MHOLE
designator MTG?  (no BOM)
footprint MTGH200C125D_PL
footprint MTGH200C125D_PL
pins: 1 TP

## microSD_CONN_2
designator P?, comment MOLEX 502570-001
CONN MICRO SD R/A PUSH-PUSH SMD; Manufacturer: Molex Inc; Manufacturer Part Number: 5025700893; Card Type: Secure Digital - microSD?TransFlash; Number of Positions: 10 (8 + 2); Connector Type: Connector and Ejector; Insertion, Removal Method: Push In, Push Out
footprint SD-MICRO-SCHA5B0300
pins: 1 DAT2, 2 CD/DAT3, 3 CMD, 4 VDD (power), 5 CLOCK, 6 VSS (power), 7 DAT0, 8 DAT1, 9 GND (power), 10 CD, 11 GND (power), 12 GND (power), 13 GND, 14 GND, 15 GND, 16 GND

## MINI-USB-AB-SOCKET
designator P?, comment mini USB-B
CONN RCPT USB MINI B R/A SMD; Manufacturer: KYCON; Manufacturer Part Number: 0565790576; Order# 2: C-440247; ATLStockNo1: 4500.0223; Order#: KMAB-SMT-5S-S-30TR; Connector Type: USB - mini AB; Number of Contacts: 5; Gender: Receptacle; Specifications: USB 2.0 OTG
footprint USB5MINI_4SHIELDED_SMD-5
pins: 1 VB, 2 D-, 3 D+, 4 ID, 5 G1, 6 G3, 7 G2, 8 G5, 9 G4

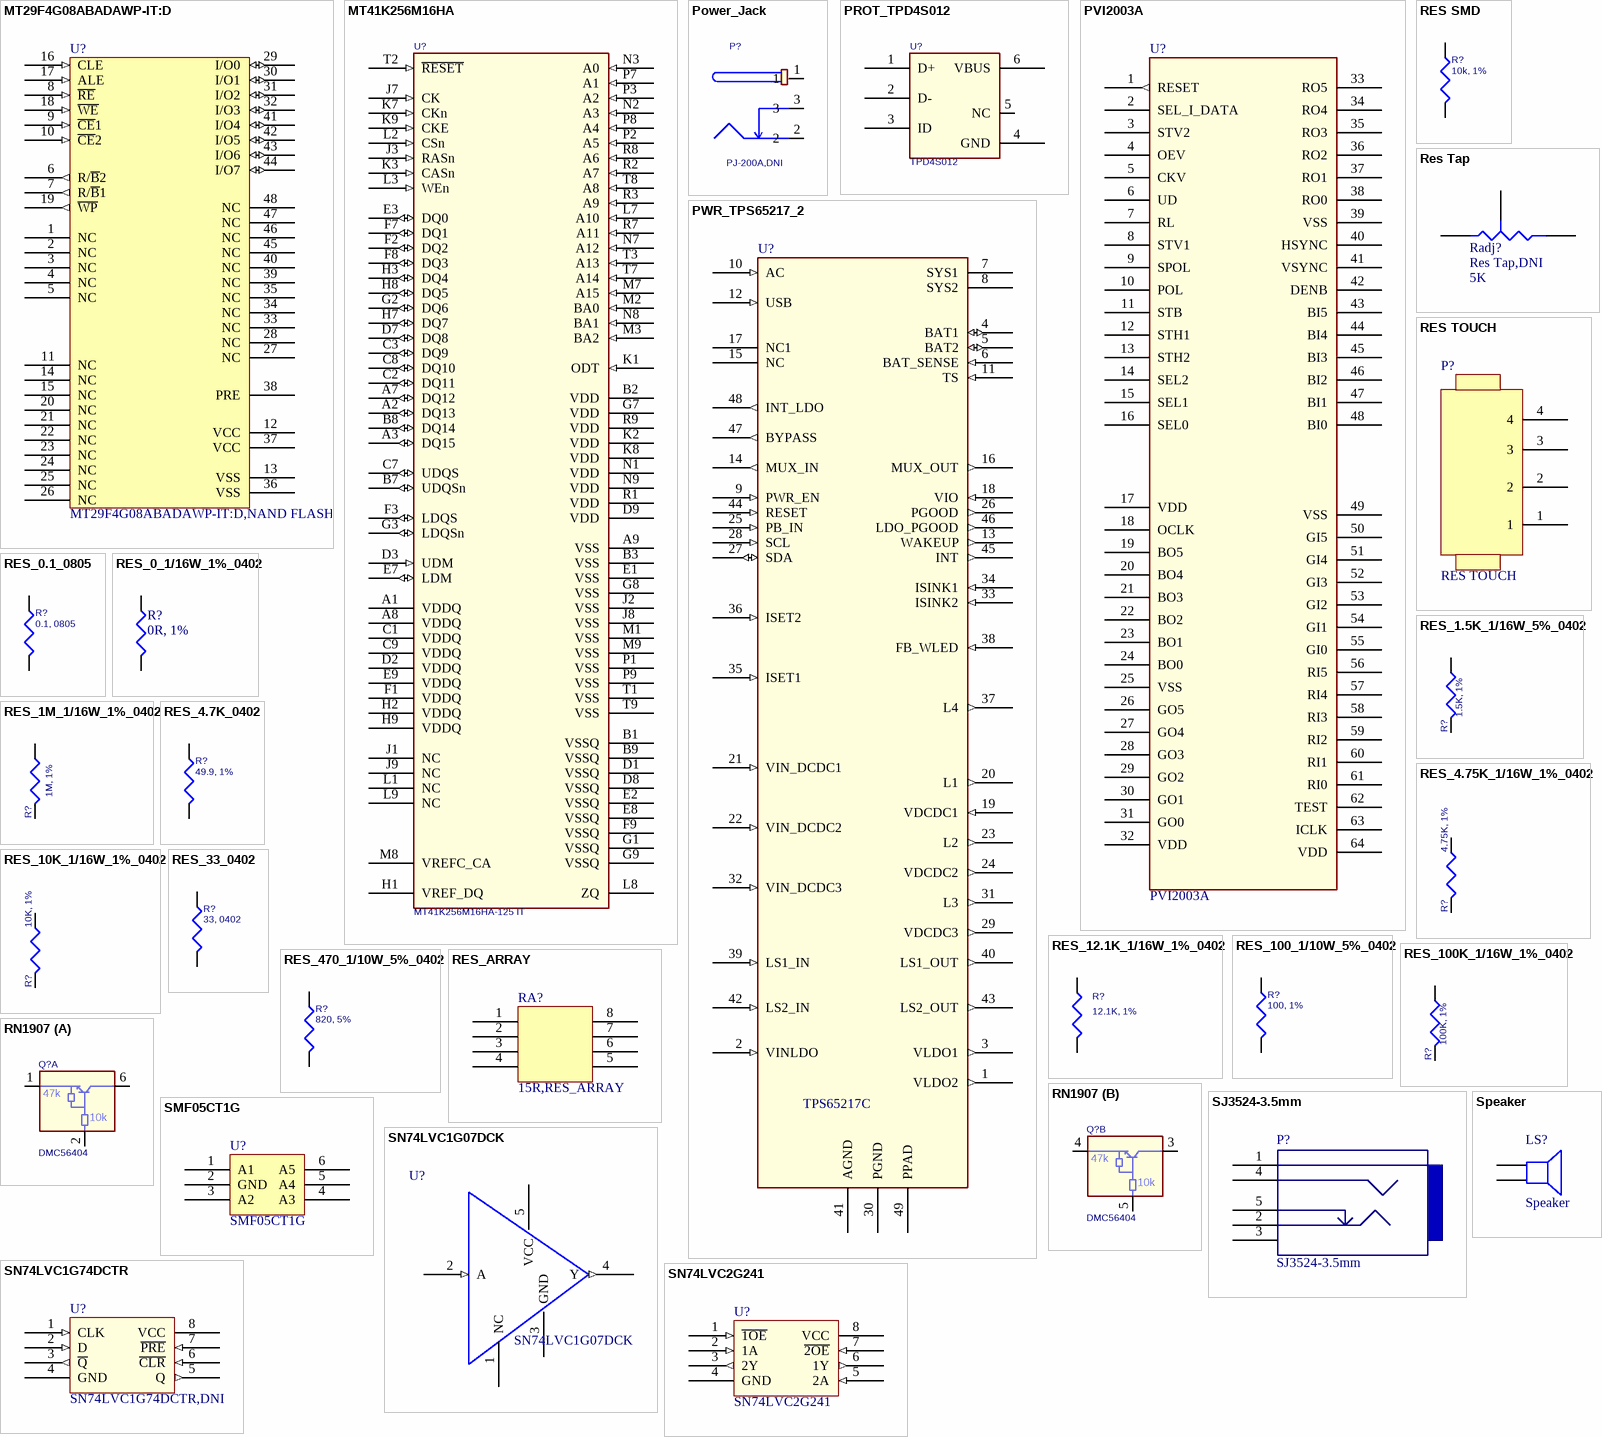
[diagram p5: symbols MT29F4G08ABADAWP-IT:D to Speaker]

## MT29F4G08ABADAWP-IT:D
designator U?, comment MT29F4G08ABADAWP-IT:D,NAND FLASH
footprint MT29F4G08ABADAWP-ITD (Footprint not found)
pins: 1 NC, 2 NC, 3 NC, 4 NC, 5 NC, 6 R/~{B}2 (out), 7 R/~{B}1 (out), 8 ~{RE} (in), 9 ~{CE}1 (in), 10 ~{CE}2 (in), 11 NC, 12 VCC, 13 VSS, 14 NC, 15 NC, 16 CLE (in), 17 ALE (in), 18 ~{WE} (in), 19 ~{WP} (out), 20 NC, 21 NC, 22 NC, 23 NC, 24 NC, 25 NC, 26 NC, 27 NC, 28 NC, 29 I/O0 (io), 30 I/O1 (io), 31 I/O2 (io), 32 I/O3 (io), 33 NC, 34 NC, 35 NC, 36 VSS, 37 VCC, 38 PRE, 39 NC, 40 NC, 41 I/O4 (io), 42 I/O5 (io), 43 I/O6 (io), 44 I/O7 (io), 45 NC, 46 NC, 47 NC, 48 NC

## MT41K256M16HA
designator U?, comment MT41K256M16HA-125 IT
DDR2 SDRAM 2Gb (256Mx8); Manufacturer: ISSI; Manufacturer Part Number: IS43TR16256A-15HBLI; Lead Time: 0 weeks
footprint IS43TR16256A-15HBLI/MT41K256M16HA-125 IT_E TR (Footprint not found)
pins: A1 VDDQ (power), A2 DQ13 (io), A3 DQ15 (io), A7 DQ12 (io), A8 VDDQ (power), A9 VSS (power), B1 VSSQ (power), B2 VDD (power), B3 VSS (power), B7 UDQSn (io), B8 DQ14 (io), B9 VSSQ (power), C1 VDDQ (power), C2 DQ11 (io), C3 DQ9 (io), C7 UDQS (io), C8 DQ10 (io), C9 VDDQ (power), D1 VSSQ (power), D2 VDDQ (power), D3 UDM (in), D7 DQ8 (io), D8 VSSQ (power), D9 VDD (power), E1 VSS (power), E2 VSSQ (power), E3 DQ0 (io), E7 LDM (io), E8 VSSQ (power), E9 VDDQ (power), F1 VDDQ (power), F2 DQ2 (io), F3 LDQS (io), F7 DQ1 (io), F8 DQ3 (io), F9 VSSQ (power), G1 VSSQ (power), G2 DQ6 (io), G3 LDQSn (io), G7 VDD (power), G8 VSS (power), G9 VSSQ (power), H1 VREF_DQ, H2 VDDQ (power), H3 DQ4 (io), H7 DQ7 (io), H8 DQ5 (io), H9 VDDQ (power), J1 NC, J2 VSS (power), J3 RASn (in), J7 CK (in), J8 VSS (power), J9 NC, K1 ODT (in), K2 VDD (power), K3 CASn (in), K7 CKn (in), K8 VDD (power), K9 CKE (in), L1 NC (power), L2 CSn (in), L3 WEn (in), L7 A10 (in), L8 ZQ, L9 NC (power), M1 VSS (power), M2 BA0 (in), M3 BA2 (in), M7 A15 (in), M8 VREFC_CA (power), M9 VSS (power), N1 VDD (power), N2 A3 (in), N3 A0 (in), N7 A12 (in), N8 BA1 (in), N9 VDD (power), P1 VSS (power), P2 A5 (in), P3 A2 (in), P7 A1 (in), P8 A4 (in), P9 VSS (power), R1 VDD (power), R2 A7 (in), R3 A9 (in), R7 A11 (in), R8 A6 (in), R9 VDD (power), T1 VSS (power), T2 ~{RESET} (in), T3 A13 (in), T7 A14 (in), T8 A8 (in), T9 VSS (power)

## Power_Jack
designator P?, comment PJ-200A,DNI
CONN PWR JACK 2.1X5.5MM HIGH CUR; Manufacturer: CUI Inc; Manufacturer Part Number: PJ-002AH; Gender: Male; Plug/Mating Plug Diameter: 2.1mm ID, 5.5mm OD; Number of Positions/Contacts: 2 Conductors, 3 Contacts; Internal Switch(s): Single Switch, Normally Closed; Shielding: Unshielded; Current Rating: 5A
footprint CONN3-PWR-PJ102A
pins: 1, 2, 3

## PROT_TPD4S012
designator U?, comment TPD4S012
ESD 4channel USB Interface; Mfr: TI; MfrNum: TPD4S012DRY; TIIntPartnumber: 1A0233; Manufacturer: Texas Instruments; Manufacturer Part Number: TPD4S012DRYR; Vendor: Digikey; Cost100: 0.76; Cost10K: 0.23; Power (Watts): 60W; Number of Circuits: 4
footprint U_6_DRY/TPD4S012DRYR/6-SON (Footprint not found)
footprint U_6_DRY
pins: 1 D+, 2 D-, 3 ID, 4 GND (power), 5 NC, 6 VBUS (power)

## PVI2003A
designator U?
footprint TQFP13-64 STD/PVI2003A (Footprint not found)
pins: 1 RESET (out), 2 SEL_I_DATA, 3 STV2, 4 OEV, 5 CKV, 6 UD, 7 RL, 8 STV1, 9 SPOL, 10 POL, 11 STB, 12 STH1, 13 STH2, 14 SEL2, 15 SEL1, 16 SEL0, 17 VDD, 18 OCLK, 19 BO5, 20 BO4, 21 BO3, 22 BO2, 23 BO1, 24 BO0, 25 VSS, 26 GO5, 27 GO4, 28 GO3, 29 GO2, 30 GO1, 31 GO0, 32 VDD, 33 RO5, 34 RO4, 35 RO3, 36 RO2, 37 RO1, 38 RO0, 39 VSS, 40 HSYNC, 41 VSYNC, 42 DENB, 43 BI5, 44 BI4, 45 BI3, 46 BI2, 47 BI1, 48 BI0, 49 VSS, 50 GI5, 51 GI4, 52 GI3, 53 GI2, 54 GI1, 55 GI0, 56 RI5, 57 RI4, 58 RI3, 59 RI2, 60 RI1, 61 RI0, 62 TEST, 63 ICLK, 64 VDD

## PWR_TPS65217_2
designator U?, comment TPS65217C
IC PMIC BATT PWR SYST 48VQFN; Manufacturer: Texas Instruments; Manufacturer Part Number: TPS65217CRSLR; Voltage - Supply: 2.75 V ~ 5.8 V
footprint U_48_RSL/TPS65217CRSL/RSL (Footprint not found)
pins: 1 VLDO2 (out), 2 VINLDO (in), 3 VLDO1 (out), 4 BAT1 (io), 5 BAT2 (io), 6 BAT_SENSE (in), 7 SYS1, 8 SYS2, 9 PWR_EN (in), 10 AC (in), 11 TS (in), 12 USB (in), 13 WAKEUP (out), 14 MUX_IN (out), 15 NC, 16 MUX_OUT (out), 17 NC1, 18 VIO (in), 19 VDCDC1 (in), 20 L1 (out), 21 VIN_DCDC1 (in), 22 VIN_DCDC2 (in), 23 L2 (out), 24 VDCDC2 (out), 25 PB_IN (in), 26 PGOOD (out), 27 SDA (io), 28 SCL (in), 29 VDCDC3 (out), 30 PGND (power), 31 L3 (out), 32 VIN_DCDC3 (in), 33 ISINK2 (in), 34 ISINK1 (in), 35 ISET1 (in), 36 ISET2 (in), 37 L4 (out), 38 FB_WLED (in), 39 LS1_IN (in), 40 LS1_OUT (out), 41 AGND (power), 42 LS2_IN (in), 43 LS2_OUT (out), 44 RESET (in), 45 INT (out), 46 LDO_PGOOD (out), 47 BYPASS (out), 48 INT_LDO (out), 49 PPAD (power)

## RES SMD
designator R?, comment 10k, 1%
RES 10K OHM 1/16W 5% 0402 SMD; Manufacturer: Rohm Semiconductor; Manufacturer Part Number: MCR01MZPJ103; Power (Watts): 0.063W, 1/16W; Temperature Coefficient: ?00ppm/°C; Tolerance: ?%
footprint 402
footprint R0402
pins: 1 P1, 2 P2

## Res Tap
designator Radj?, comment Res Tap,DNI  value 5K
Tapped Resistor; Sim Note: Enter the Resistance value and the set point into parameter fields.; Set Position: 0.5
footprint RADJ (Footprint not found)
pins: 1 A, 2 B, 3 TAP

## RES TOUCH
designator P?
footprint FPC_4X1.8MM (Footprint not found)
pins: 1, 2, 3, 4

## RES_0.1_0805
designator R?, comment 0.1, 0805
RES .10 OHM 1/8W 5% 0805; Manufacturer: CTS Resistor Products; Manufacturer Part Number: 73L3R10J; Resistance (Ohms): 0.1; Power (Watts): 0.125W, 1/8W; Temperature Coefficient: ?00ppm/°C; Tolerance: ?%
footprint 805
footprint R0805
pins: 1, 2

## RES_0_1/16W_1%_0402
designator R?, comment 0R, 1%
RES 0.0 OHM 1/16W 0402 SMD; Manufacturer: Yageo; Manufacturer Part Number: RC0402JR-070RL; Power (Watts): 0.063W, 1/16W; Resistance (Ohms): 0.0; Tolerance: Jumper
footprint 402
footprint R0402
pins: 1, 2

## RES_1.5K_1/16W_5%_0402
designator R?, comment 1.5K, 1%
RES 1.50K OHM 1/16W 1% 0402 SMD; Manufacturer: Yageo; Manufacturer Part Number: RC0402FR-071K5L; Power (Watts): 0.063W, 1/16W; Temperature Coefficient: ?00ppm/°C; Tolerance: ?%
footprint 402
footprint 402
footprint R0402
pins: 1, 2

## RES_1M_1/16W_1%_0402
designator R?, comment 1M, 1%
Resistor 1Mohm 1/16W 1% 0402; Manufacturer: Stackpole Electronics Inc; Manufacturer Part Number: RMCF0402FT1M00; Power (Watts): 0.063W, 1/16W; Temperature Coefficient: ?00ppm/°C; Tolerance: ?%
footprint 402
footprint 402
footprint R0402
pins: 1, 2

## RES_4.7K_0402
designator R?, comment 49.9, 1%
RES 49.9 OHM 1/16W 1% 0402 SMD; Manufacturer: Yageo; Manufacturer Part Number: RC0402FR-0749R9L; Resistance (Ohms): 49.9; Power (Watts): 0.063W, 1/16W; Temperature Coefficient: ?00ppm/°C; Tolerance: ?%
footprint 402
footprint R0402
pins: 1, 2

## RES_4.75K_1/16W_1%_0402
designator R?, comment 4.75K, 1%
RES 4.75K OHM 1/16W 1% 0402 SMD; Manufacturer: Stackpole Electronics Inc; Manufacturer Part Number: RMCF0402FT4K75; Power (Watts): 0.063W, 1/16W; Temperature Coefficient: ?00ppm/°C; Tolerance: ?%
footprint 402
footprint 402
footprint R0402
pins: 1, 2

## RES_10K_1/16W_1%_0402
designator R?, comment 10K, 1%
RES 10K OHM 1/16W 5% 0402 SMD; Manufacturer: Rohm Semiconductor; Manufacturer Part Number: MCR01MZPJ103; Power (Watts): 0.063W, 1/16W; Temperature Coefficient: ?00ppm/°C; Tolerance: ?%
footprint 402
footprint 402
footprint R0402
pins: 1, 2

## RES_12.1K_1/16W_1%_0402
designator R?, comment 12.1K, 1%
RES 12.1K OHM 1/16W 1% 0402 SMD; Manufacturer: Yageo; Manufacturer Part Number: RC0402FR-0712K1L; Power (Watts): 0.063W, 1/16W; Temperature Coefficient: ?00ppm/°C; Tolerance: ?%
footprint 402
footprint 402
footprint R0402
pins: 1, 2

## RES_33_0402
designator R?, comment 33, 0402
RES 33 OHM 1/16W 5% 0402 SMD; Manufacturer: Panasonic Electronic Components; Manufacturer Part Number: ERJ-2GEJ330X; Resistance (Ohms): 33; Power (Watts): 0.1W, 1/10W; Temperature Coefficient: ?00ppm/°C; Tolerance: ?%
footprint 402
footprint R0402
pins: 1, 2

## RES_100_1/10W_5%_0402
designator R?, comment 100, 1%
RES 100 OHM 1/10W 5% 0402 SMD; Manufacturer: Panasonic Electronic Components; Manufacturer Part Number: ERJ-2RKF1000X; Resistance (Ohms): 100; Power (Watts): 0.1W, 1/10W; Temperature Coefficient: ?00ppm/°C; Tolerance: ?%
footprint 402
footprint 402
footprint R0402
pins: 1, 2

## RES_100K_1/16W_1%_0402
designator R?, comment 100K, 1%
RES 100K OHM 1/16W 1% 0402 SMD; Manufacturer: Stackpole Electronics Inc; Manufacturer Part Number: RMCF0402FT100K; Power (Watts): 0.063W, 1/16W; Temperature Coefficient: ?00ppm/°C; Tolerance: ?%
footprint 402
footprint 402
footprint R0402
pins: 1, 2

## RES_470_1/10W_5%_0402
designator R?, comment 820, 5%
RES 820 OHM 1/10W 5% 0402 SMD; Manufacturer: Yageo; Manufacturer Part Number: RC0402JR-07820RL; Resistance (Ohms): 820; Power (Watts): 0.063W, 1/16W; Temperature Coefficient: ?00ppm/°C; Tolerance: ?%
footprint 402
footprint 402
footprint R0402
pins: 1, 2

## RES_ARRAY
designator RA?, comment 15R,RES_ARRAY
footprint RES_ARRAY0603 (Footprint not found)
pins: 1, 2, 3, 4, 5, 6, 7, 8

## RN1907
designator Q?, comment DMC56404
TRANS PREBIASED DUAL NPN SOT363; Manufacturer: Toshiba; Manufacturer Part Number: DDC114YU-7-F; Order# 2: BCR135S; ATLStockNo1: 2130.0137; ATLStockNo2: 2130.01; Transistor Type: 2 NPN - Pre-Biased (Dual); Current - Collector (Ic) (Max): 100mA; Voltage - Collector Emitter Breakdown (Max): 50V; Resistor - Base (R1) (Ohms): 10k; Resistor - Emitter Base (R2) (Ohms): 47k; DC Current Gain (hFE) (Min) @ Ic, Vce: 68 @ 10mA, 5V; Vce Saturation (Max) @ Ib, Ic: 300mV @ 250µA, 5mA; Current - Collector Cutoff (Max): 500nA; Frequency - Transition: 250MHz; Power - Max: 200mW
footprint SMini6-F3-B
part A pins: 1 4, 2 5, 6 3
part B pins: 3, 4, 5

## SJ3524-3.5mm
designator P?
footprint jack_audio1 (Footprint not found)
pins: 1, 2, 3, 4, 5

## SMF05CT1G
designator U?
footprint SMF05CT1G/SC-88 (Footprint not found)
pins: 1 A1, 2 GND, 3 A2, 4 A3, 5 A4, 6 A5

## SN74LVC1G07DCK
designator U?
footprint SN74LVC1G07DCK/SOT-DCK (Footprint not found)
pins: 1 NC, 2 A (in), 3 GND, 4 Y (out), 5 VCC

## SN74LVC1G74DCTR
designator U?, comment SN74LVC1G74DCTR,DNI
SINGLE  POSITIVE-EDGE-TRIGGERED  D-TYPE  FLIP-FLOP WITH  CLEAR  AND  PRESET; Manufacturer: Texas Instruments; Function: Set(Preset) and Reset; Output Type: Differential; Number of Elements: 1; Frequency - Clock: 200MHz; Delay Time - Propagation: 1.6ns; Trigger Type: Positive Edge; Current - Output High, Low: 32mA, 32mA; Voltage - Supply: 1.65 V ~ 5.5 V
footprint SOP8_DCT/SN74LVC1G74DCTR/SSOP-DCT (Footprint not found)
pins: 1 CLK (in), 2 D (in), 3 ~{Q} (out), 4 GND (power), 5 Q (out), 6 ~{CLR} (in), 7 ~{PRE} (in), 8 VCC (power)

## SN74LVC2G241
designator U?
IC BUFF/DVR TRI-ST DL 8VSSOP; Manufacturer: Texas Instruments; Manufacturer Part Number: SN74LVC2G241DCUR; Logic Type: Buffer/Line Driver, Non-Inverting; Number of Elements: 2; Number of Bits per Element: 1; Current - Output High, Low: 32mA, 32mA; Voltage - Supply: 1.65 V ~ 5.5 V
footprint U_8_DCU/SN74LVC2G241DCUR/US8 (Footprint not found)
pins: 1 ~{1OE} (in), 2 1A (in), 3 2Y (out), 4 GND (power), 5 2A (in), 6 1Y (out), 7 ~{2OE} (in), 8 VCC (power)

## Speaker
designator LS?
Loudspeaker
footprint PIN2 (Loudspeaker; 2 Leads)
pins: 1, 2

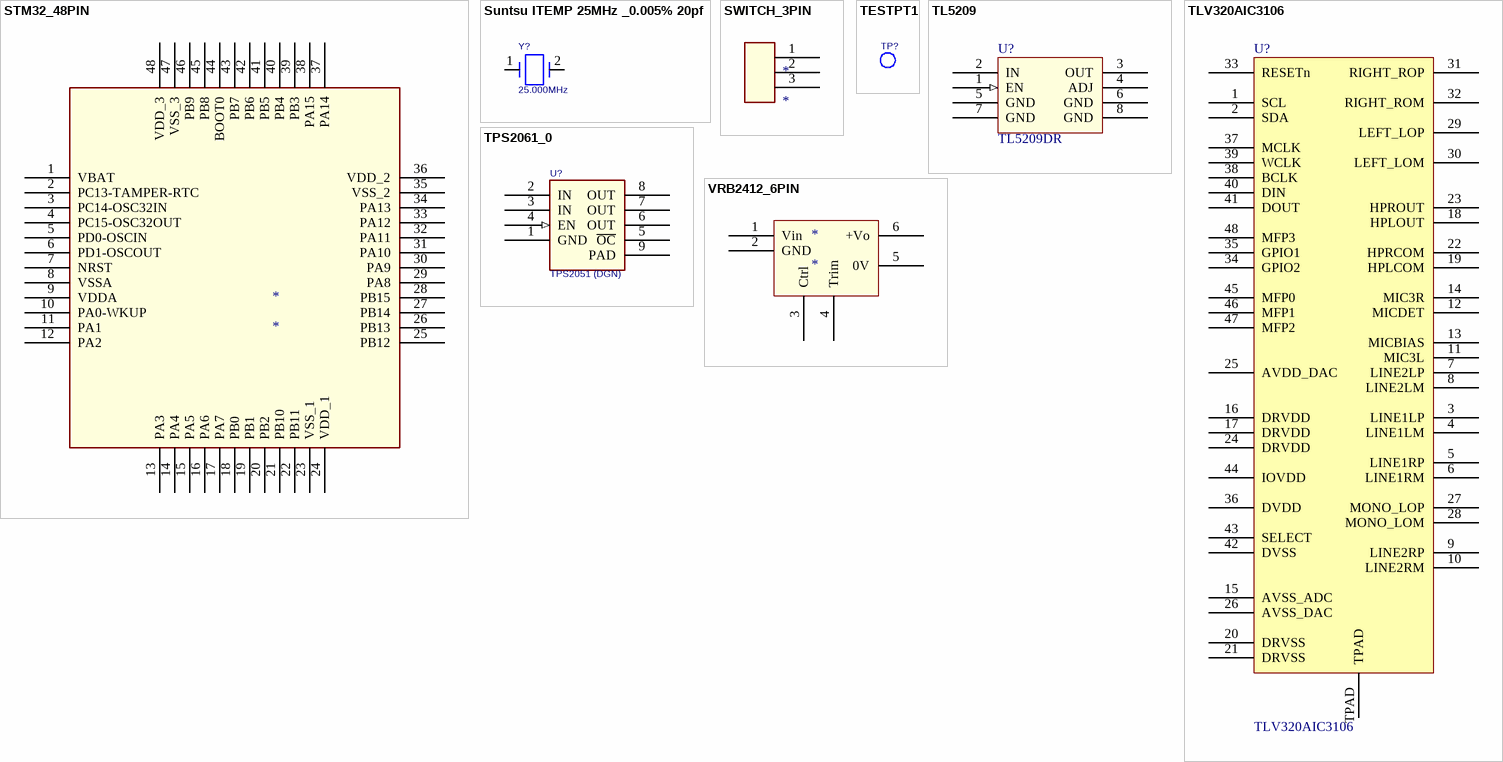
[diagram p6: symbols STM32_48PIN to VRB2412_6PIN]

## STM32_48PIN
designator *
pins: 1 VBAT, 2 PC13-TAMPER-RTC, 3 PC14-OSC32IN, 4 PC15-OSC32OUT, 5 PD0-OSCIN, 6 PD1-OSCOUT, 7 NRST, 8 VSSA, 9 VDDA, 10 PA0-WKUP, 11 PA1, 12 PA2, 13 PA3, 14 PA4, 15 PA5, 16 PA6, 17 PA7, 18 PB0, 19 PB1, 20 PB2, 21 PB10, 22 PB11, 23 VSS_1, 24 VDD_1, 25 PB12, 26 PB13, 27 PB14, 28 PB15, 29 PA8, 30 PA9, 31 PA10, 32 PA11, 33 PA12, 34 PA13, 35 VSS_2, 36 VDD_2, 37 PA14, 38 PA15, 39 PB3, 40 PB4, 41 PB5, 42 PB6, 43 PB7, 44 BOOT0, 45 PB8, 46 PB9, 47 VSS_3, 48 VDD_3

## Suntsu ITEMP 25MHz _0.005% 20pf
designator Y?, comment 25.000MHz
Manufacturer: Abracon Corporation; Manufacturer Part Number: ABM3-25.000MHZ-B2-T; Frequency: 25MHz; Frequency Stability: ?0ppm; Load Capacitance: 18pF; ESR (Equivalent Series Resistance): 50 Ohm; Operating Mode: Fundamental
footprint XTAL150SMD_125X196
pins: 1, 2

## SWITCH_3PIN
designator *
pins: 1 (power), 2, 3

## TESTPT1
designator TP?  (value not drawn)  (no BOM)
footprint tp1-8040
footprint tp1-8040
pins: 1 TP

## TL5209
designator U?, comment TL5209DR
IC LDO VOLT REG 500MA 8-SOIC; Manufacturer: Texas Instruments; Regulator Topology: Positive Adjustable; Voltage - Output: 2.5 V ~ 6.5 V; Voltage - Input: 2.5 V ~ 16 V; Voltage - Dropout (Typical): 0.35V @ 500mA; Number of Regulators: 1; Current - Output: 500mA (Max)
footprint SO8-25X75/TL5209DR/8-SOIC (Footprint not found)
pins: 1 EN (in), 2 IN (power), 3 OUT (power), 4 ADJ, 5 GND (power), 6 GND (power), 7 GND (power), 8 GND (power)

## TLV320AIC3106
designator U?
footprint TLV320AIC3106/QFN-48 (Footprint not found)
pins: 1 SCL, 2 SDA, 3 LINE1LP, 4 LINE1LM, 5 LINE1RP, 6 LINE1RM, 7 LINE2LP, 8 LINE2LM, 9 LINE2RP, 10 LINE2RM, 11 MIC3L, 12 MICDET, 13 MICBIAS, 14 MIC3R, 15 AVSS_ADC, 16 DRVDD, 17 DRVDD, 18 HPLOUT, 19 HPLCOM, 20 DRVSS, 21 DRVSS, 22 HPRCOM, 23 HPROUT, 24 DRVDD, 25 AVDD_DAC, 26 AVSS_DAC, 27 MONO_LOP, 28 MONO_LOM, 29 LEFT_LOP, 30 LEFT_LOM, 31 RIGHT_ROP, 32 RIGHT_ROM, 33 RESETn, 34 GPIO2, 35 GPIO1, 36 DVDD, 37 MCLK, 38 BCLK, 39 WCLK, 40 DIN, 41 DOUT, 42 DVSS, 43 SELECT, 44 IOVDD, 45 MFP0, 46 MFP1, 47 MFP2, 48 MFP3, TPAD

## TPS2061_0
designator U?, comment TPS2051 (DGN)
IC 1.5A PWR DIST SWITCH 8-SOIC; Manufacturer: Texas Instruments; Manufacturer Part Number: TPS2051BDGNR; Number of Outputs: 1; Rds (On): 135 mOhm; Internal Switch(s): Yes; Current Limit: 1A; Voltage - Input: 2.7 V ~ 5.5 V
footprint DGN-16X60/TPS2051BDGN/8-MSOP (Footprint not found)
pins: 1 GND (power), 2 IN (power), 3 IN (power), 4 EN (in), 5 ~{OC}, 6 OUT (power), 7 OUT (power), 8 OUT (power), 9 PAD

## VRB2412_6PIN
designator *
pins: 1 Vin, 2 GND, 3 Ctrl, 4 Trim, 5 0V, 6 +Vo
